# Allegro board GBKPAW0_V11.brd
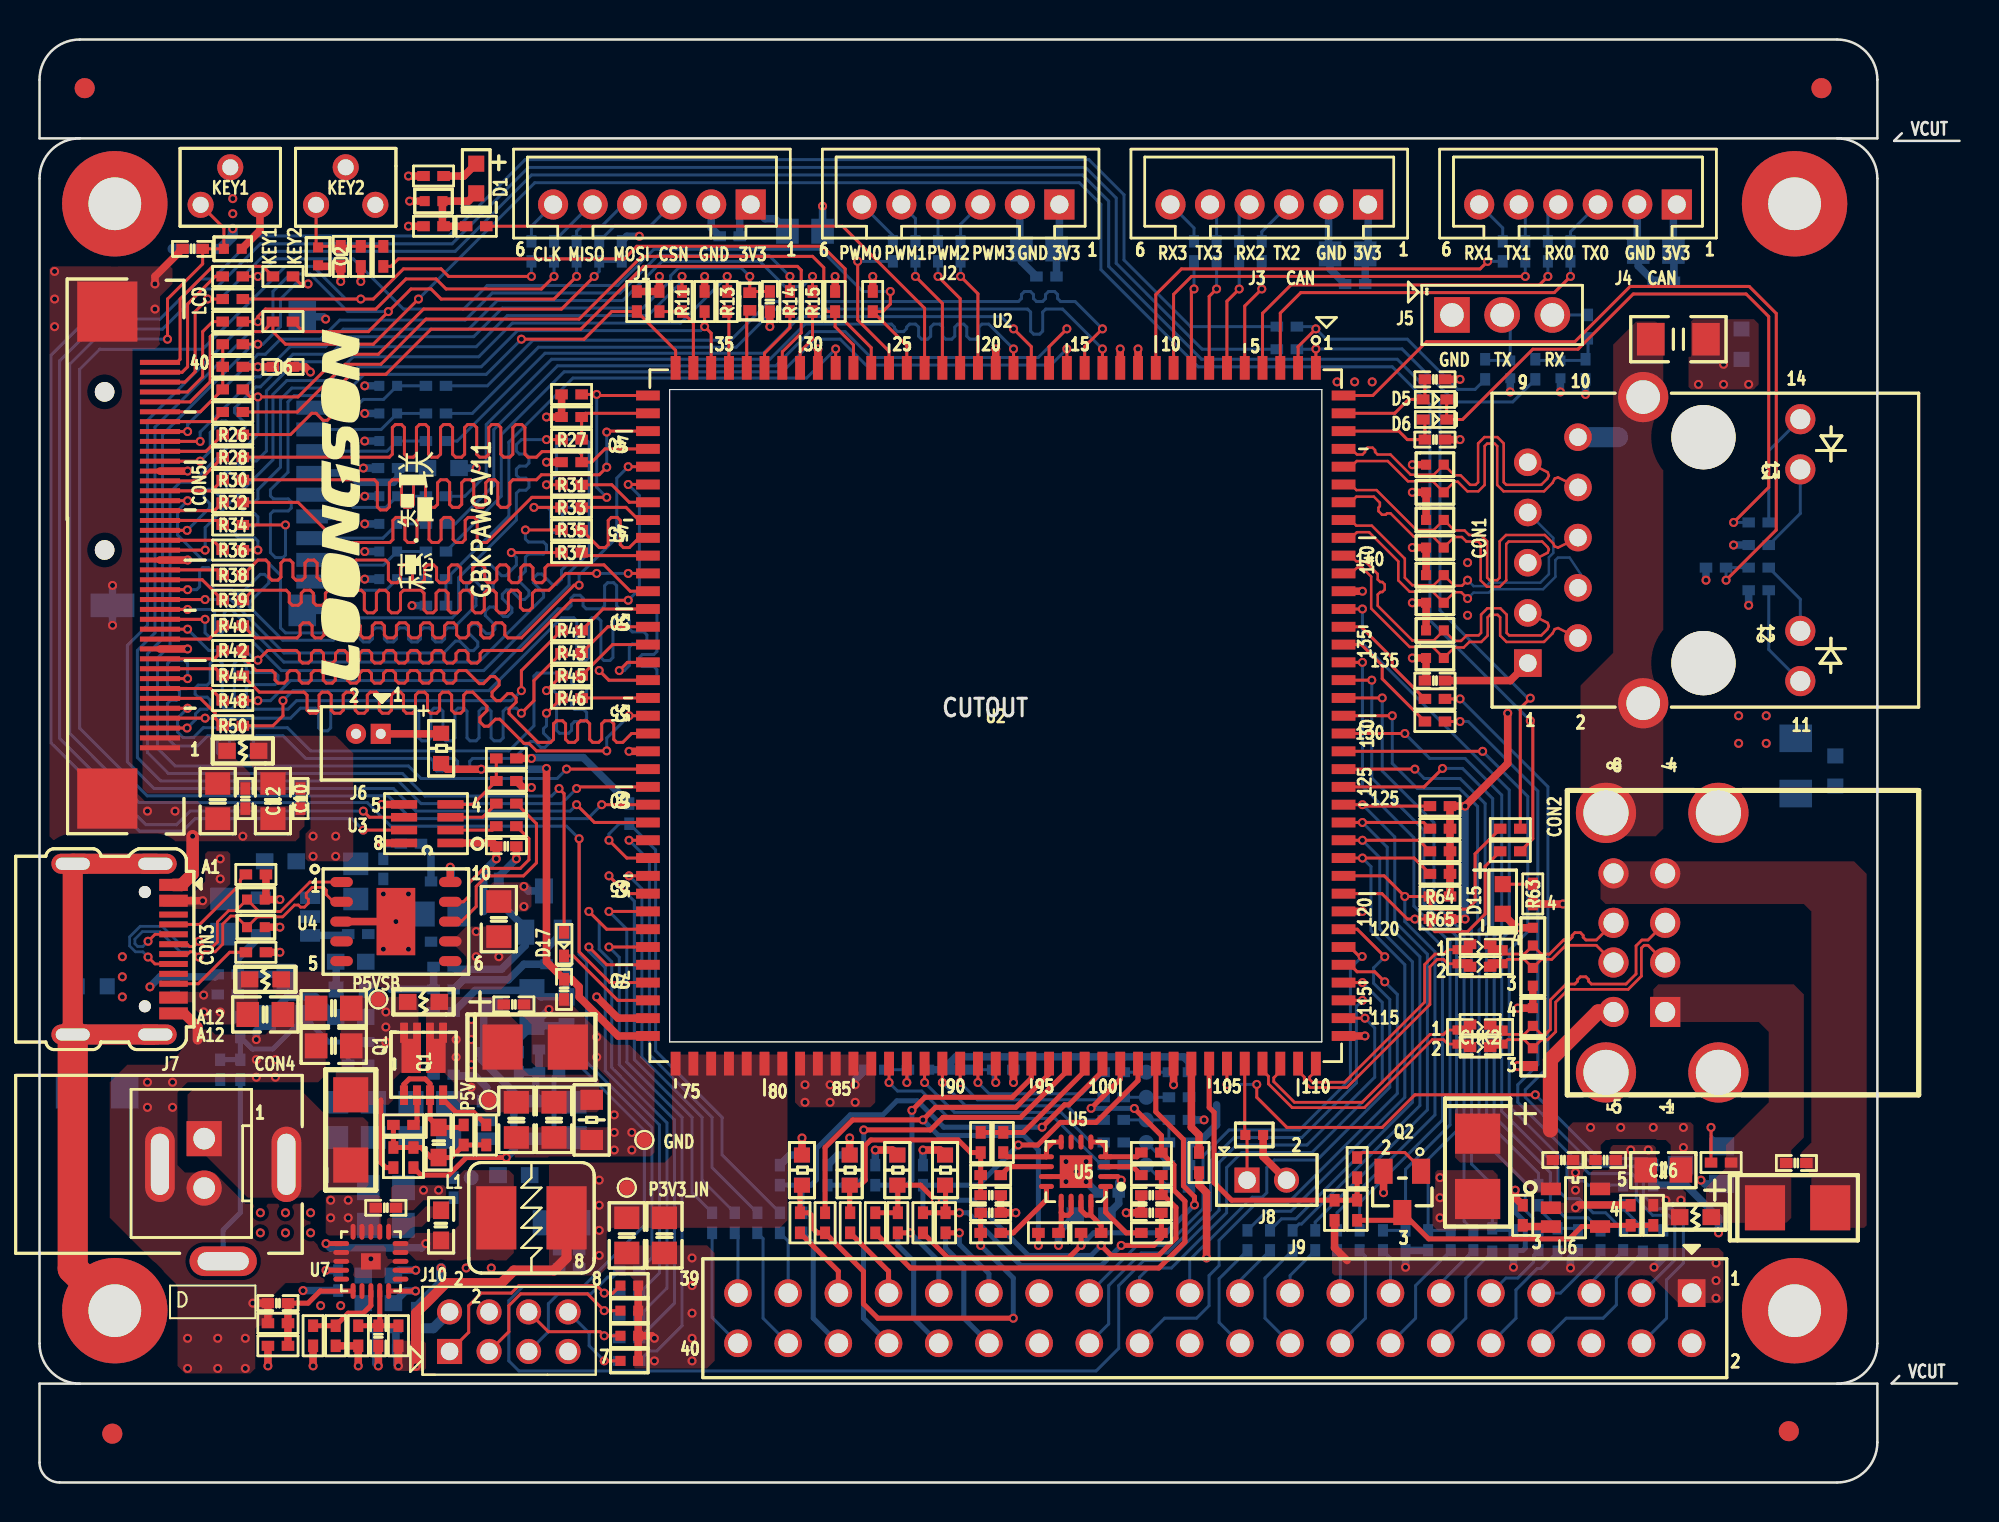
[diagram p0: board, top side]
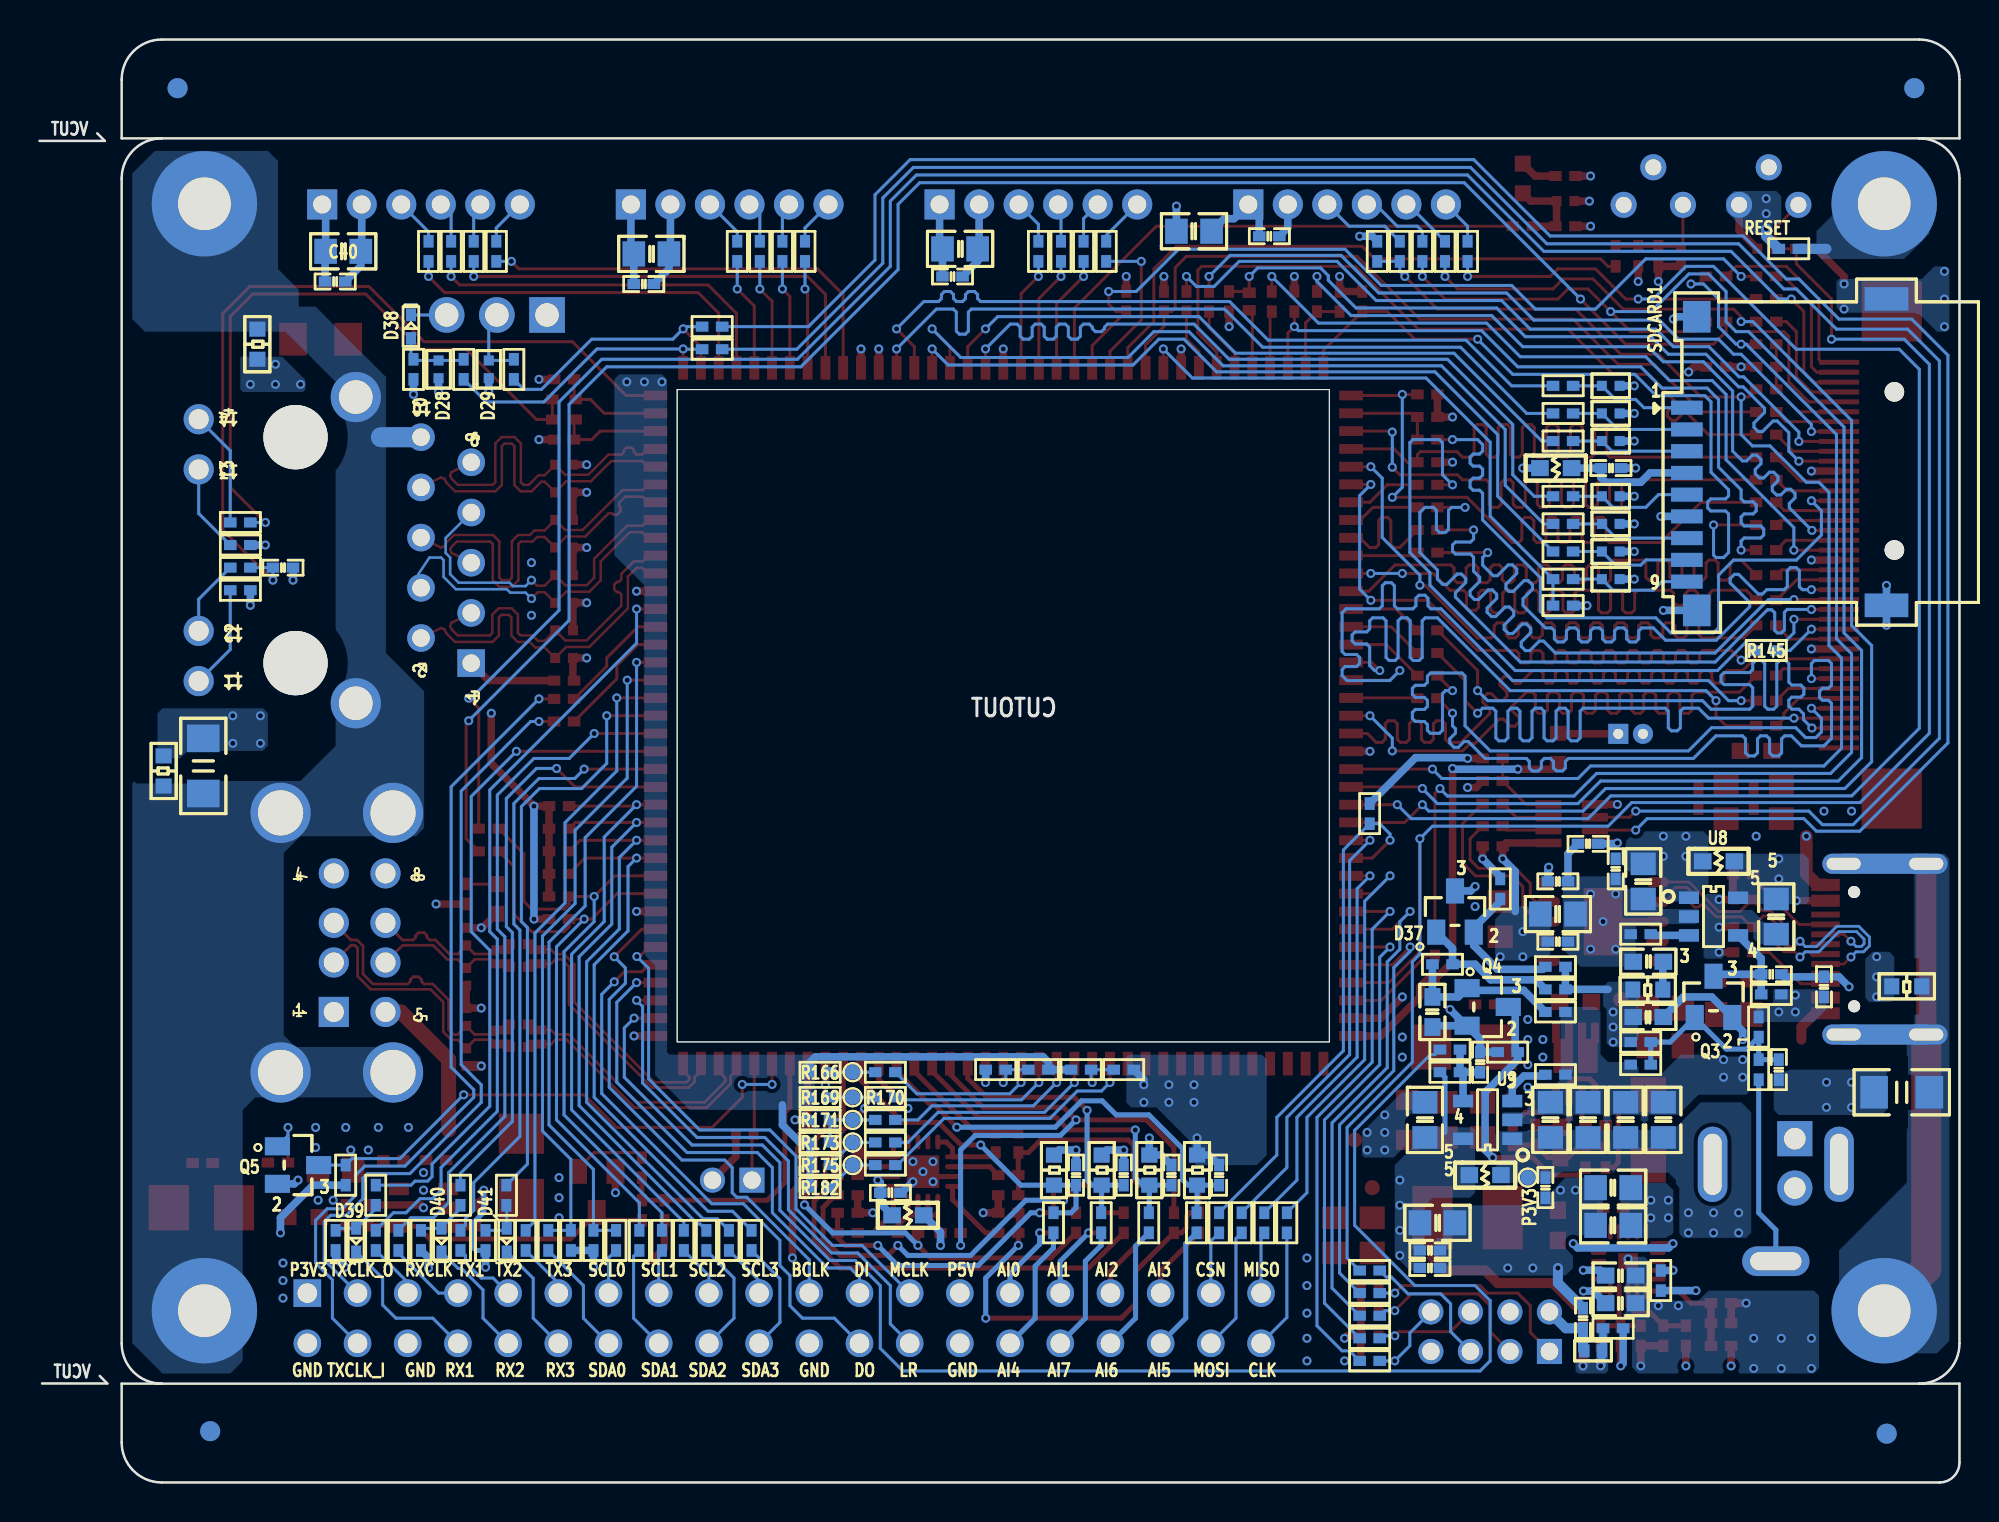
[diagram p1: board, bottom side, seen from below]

Outline 97.16 x 73 mm; copper layers: TOP, GND02, PWR03, BOTTOM. Coordinates in mm from the lower left corner of the outline.
Outline path: 2.03,68 0,68 0,70.97 arc(0.6,72.4) 2.03,73 90.97,73 arc(92.4,72.4) 93,70.97 93,68 90.97,68 ; 2.03,68 arc(0.6,67.4) 0,65.97 ; 2.03,68 arc(0.6,67.4) 0,65.97 ; 2.03,68 90.97,68 ; 2.03,68 90.97,68 ; 0,65.97 0,7.03 ; 0,65.97 0,7.03 ; 0,7.03 arc(0.6,5.6) 2.03,5 ; 0,7.03 arc(0.6,5.6) 2.03,5 ; 2.03,5 0,5 0,1.02 arc(0.3,0.3) 1.02,0 90.97,0 arc(92.4,0.6) 93,2.03 93,5 90.97,5 ; 2.03,5 90.97,5 ; 2.03,5 90.97,5 ; 90.97,68 arc(92.4,67.4) 93,65.97 ; 90.97,68 arc(92.4,67.4) 93,65.97 ; 90.97,5 arc(92.4,5.6) 93,7.03 ; 90.97,5 arc(92.4,5.6) 93,7.03 ; 93,65.97 93,7.03 ; 93,65.97 93,7.03 ; 94.11,5.39 93.73,5.01 97.03,5.01 ; 94.23,68.25 93.85,67.87 97.16,67.87 ; 31.89,55.29 31.89,22.29 64.89,22.29 64.89,55.29 31.89,55.29

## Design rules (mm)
net group CARD_DET: nets CARD_DET CPU_TIM1_CH1
net group CPU_JTAG_TCK: nets CPU_JTAG_TCK EJTAG_TCK
net group CPU_LCD_CLK: nets CPU_LCD_CLK LCD_CLK
net group CPU_LCD_DATA0: nets CPU_LCD_DATA0 LCD_B0
net group CPU_LCD_DATA1: nets CPU_LCD_DATA1 LCD_B1
net group CPU_LCD_DATA2: nets CPU_LCD_DATA2 LCD_B2
net group CPU_LCD_DATA3: nets CPU_LCD_DATA3 LCD_B3
net group CPU_LCD_DATA4: nets CPU_LCD_DATA4 LCD_B4
net group CPU_LCD_DATA5: nets CPU_LCD_DATA5 LCD_B5
net group CPU_LCD_DATA6: nets CPU_LCD_DATA6 LCD_B6
net group CPU_LCD_DATA7: nets CPU_LCD_DATA7 LCD_B7
net group CPU_LCD_DATA8: nets CPU_LCD_DATA8 LCD_G0
net group CPU_LCD_DATA9: nets CPU_LCD_DATA9 LCD_G1
net group CPU_LCD_DATA10: nets CPU_LCD_DATA10 LCD_G2
net group CPU_LCD_DATA11: nets CPU_LCD_DATA11 LCD_G3
net group CPU_LCD_DATA12: nets CPU_LCD_DATA12 LCD_G4
net group CPU_LCD_DATA13: nets CPU_LCD_DATA13 LCD_G5
net group CPU_LCD_DATA14: nets CPU_LCD_DATA14 LCD_G6
net group CPU_LCD_DATA15: nets CPU_LCD_DATA15 LCD_G7
net group CPU_LCD_DATA16: nets CPU_LCD_DATA16 LCD_R0
net group CPU_LCD_DATA17: nets CPU_LCD_DATA17 LCD_R1
net group CPU_LCD_DATA18: nets CPU_LCD_DATA18 LCD_R2
net group CPU_LCD_DATA19: nets CPU_LCD_DATA19 LCD_R3
net group CPU_LCD_DATA20: nets CPU_LCD_DATA20 LCD_R4
net group CPU_LCD_DATA21: nets CPU_LCD_DATA21 LCD_R5
net group CPU_LCD_DATA22: nets CPU_LCD_DATA22 LCD_R6
net group CPU_LCD_DATA23: nets CPU_LCD_DATA23 LCD_R7
net group CPU_LCD_EN: nets CPU_LCD_EN LCD_DE
net group CPU_LCD_HSYNC: nets CPU_LCD_HSYNC LCD_HSYNC
net group CPU_LCD_VSYNC: nets CPU_LCD_VSYNC LCD_VSYNC
net group CPU_SDIO1_CLK: nets CPU_SDIO1_CLK SDIO1_CLK
net group CPU_SDIO1_CMD: nets CPU_SDIO1_CMD SDIO1_CMD
net group CPU_SDIO1_DATA0: nets CPU_SDIO1_DATA0 SDIO1_DATA0
net group CPU_SDIO1_DATA1: nets CPU_SDIO1_DATA1 SDIO1_DATA1
net group CPU_SDIO1_DATA2: nets CPU_SDIO1_DATA2 SDIO1_DATA2
net group CPU_SDIO1_DATA3: nets CPU_SDIO1_DATA3 SDIO1_DATA3
net group CPU_USB0_DM: nets CPU_USB0_DM USB0_DM
net group CPU_USB0_DP: nets CPU_USB0_DP USB0_DP
net group CPU_USB1_DM: nets CPU_USB1_DM USB1_DM
net group CPU_USB1_DP: nets CPU_USB1_DP USB1_DP
net group EARTH: nets GND_EARTH_R N21978619
net group USB_D: nets USB_DN USB_DP
net group MDIO: nets P0_MDIO0+ P0_MDIO0- P0_MDIO2+ P0_MDIO2- P0_MDIO3+ P0_MDIO3-
nets with their own width: min track width 0.381; nets GND P3V3

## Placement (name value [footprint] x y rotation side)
C1  -  [C0402]  7.75 62.41 180 top
C2  -  [C0402]  15.24 62.03 270 top
C3  -  [C0402]  36.96 59.75 270 top
C4  -  [C1206]  82.93 57.84 180 top
C5  -  [C0402]  70.61 55.81 180 top
C6  -  [C0402]  12.32 56.44 0 top
C7  -  [C0402]  70.61 52.76 180 top
C8  -  [C0402]  70.61 40.57 180 top
C9  -  [C0402]  10.41 34.6 270 top
C10  -  [C0402]  13.21 34.6 270 top
C11  -  [C0805]  9.02 34.47 270 top
C12  -  [C0805]  11.81 34.47 270 top
C13  -  [C0402]  23.62 32.19 0 top
C14  -  [C0805]  23.24 28.5 270 top
C15  -  [C0402]  26.54 24.95 90 top
C16  -  [C0402]  24 24.19 0 top
C17  -  [C0805]  14.89 23.99 180 top
C18  -  [C0805]  11.43 23.68 180 top
C19  -  [C0805]  14.89 22.09 180 top
C20  -  [C0805]  24.13 18.34 270 top
C21  -  [C0805]  26.04 18.34 270 top
C22  -  [C0603]  20.19 17.2 90 top
C23  -  [C0402]  77.09 16.31 0 top
C24  -  [C0402]  79.25 16.31 180 top
C25  -  [C0402]  88.9 16.16 0 top
C26  -  [C0805]  82.17 15.8 0 top
C27  -  [C0402]  48.13 14.53 180 top
C28  -  [C0402]  56.26 14.53 0 top
C29  -  [C0402]  17.53 13.9 180 top
C30  -  [C0402]  48.13 13.64 180 top
C31  -  [C0402]  56.26 13.64 0 top
C32  -  [C0603]  20.32 13.01 270 top
C33  -  [C0805]  29.72 12.5 270 top
C34  -  [C0805]  31.62 12.5 270 top
C35  -  [C0402]  12.06 9.07 0 top
C36  -  [C0402]  17.14 7.42 270 top
C37  -  [C0805]  38.73 63.3 0 bottom
C38  -  [C0402]  34.92 63.05 180 bottom
C39  -  [C0805]  50.57 62.41 180 bottom
C40  -  [C0805]  81.79 62.29 180 bottom
C41  -  [C0805]  66.19 62.15 180 bottom
C42  -  [C0402]  50.95 61.01 180 bottom
C43  -  [C0402]  82.2 60.76 180 bottom
C44  -  [C0402]  66.58 60.63 180 bottom
C45  -  [C0402]  17.64 51.32 180 bottom
C46  -  [C0402]  84.84 46.28 0 bottom
C47  -  [C1206]  88.87 36.25 270 bottom
C48  -  [C0402]  18.8 32.31 0 bottom
C49  -  [C0402]  17.4 31.04 270 bottom
C50  -  [C0402]  20.32 30.41 180 bottom
C51  -  [C0805]  16 30.41 270 bottom
C52  -  [C0805]  20.32 28.76 0 bottom
C53  -  [C0805]  9.27 28.63 270 bottom
C54  -  [C0402]  20.32 27.36 180 bottom
C55  -  [C0603]  15.75 26.34 0 bottom
C56  -  [C0402]  9.52 25.71 180 bottom
C57  -  [C0402]  6.86 25.07 90 bottom
C58  -  [C0603]  26.67 23.8 270 bottom
C59  -  [C0603]  15.75 23.55 180 bottom
C60  -  [C0402]  24.26 21.26 270 bottom
C61  -  [C0402]  9.14 20.88 270 bottom
C62  -  [C1206]  2.92 19.74 180 bottom
C63  -  [C0805]  27.05 18.34 90 bottom
C64  -  [C0805]  20.7 18.34 90 bottom
C65  -  [C0805]  18.8 18.34 90 bottom
C66  -  [C0805]  16.89 18.34 90 bottom
C67  -  [C0805]  14.99 18.34 90 bottom
C68  -  [C0402]  44.7 15.55 270 bottom
C69  -  [C0402]  42.29 15.55 270 bottom
C70  -  [C0402]  39.88 15.55 270 bottom
C71  -  [C0402]  37.47 15.55 270 bottom
C72  -  [C0402]  20.95 14.91 270 bottom
C73  -  [C0805]  17.53 14.91 0 bottom
C74  -  [C0402]  54.1 14.66 0 bottom
C75  -  [C0805]  26.42 13.14 180 bottom
C76  -  [C0805]  17.53 13.01 0 bottom
C77  -  [C0402]  26.8 11.74 0 bottom
C78  -  [C0402]  26.8 10.85 0 bottom
C79  -  [C0603]  17.14 10.47 180 bottom
C80  -  [C0603]  17.14 9.07 180 bottom
C81  -  [C0402]  19.05 8.31 270 bottom
CHK1  -  [FB4-0805]  72.9 26.6 270 top
CHK2  -  [FB4-0805]  72.9 22.53 270 top
CON1  -  [RJ45-10-100-LED2-M]  75.31 41.45 270 top
CON2  -  [USB8-H-2X1_2]  82.26 23.8 90 top
CON3  TYPE_C_20  [TYPE_C_20_2]  2.73 26.98 270 top
CON4  -  [PWC3-250_2]  12.49 16.1 270 top
CON5  -  [FPC40-20]  6.1 46.92 270 top
D1  LED BLUE  [LEDS_19_21SYGC]  22.1 65.97 90 top
D2  -  [ESDPSA-0402]  19.94 64.83 0 top
D3  -  [ESDPSA-0402]  9.78 62.41 180 top
D4  -  [ESDPSA-0402]  14.1 62.03 90 top
D5  -  [DIODE_SOD923]  70.61 54.79 180 top
D6  -  [DIODE_SOD923]  70.61 53.78 180 top
D7  -  [ESDPSA-0402]  70.61 51.49 0 top
D8  -  [ESDPSA-0402]  70.61 50.09 0 top
D9  -  [ESDPSA-0402]  70.61 48.7 0 top
D10  -  [ESDPSA-0402]  70.61 47.3 0 top
D11  -  [ESDPSA-0402]  70.61 45.9 0 top
D12  -  [ESDPSA-0402]  70.61 44.51 0 top
D13  -  [ESDPSA-0402]  70.61 43.11 0 top
D14  -  [ESDPSA-0402]  70.61 41.71 0 top
D15  LED BLUE  [LEDS_19_21SYGC]  74.04 29.52 90 top
D16  -  [ESDPSA-0402]  10.95 29.49 0 top
D17  -  [DIODE_SOD923]  26.54 27.23 90 top
D18  -  [ESDPSA-0402]  10.95 28.09 0 top
D19  -  [ESDPSA-0402]  75.56 27.61 90 top
D20  -  [ESDPSA-0402]  75.56 25.58 270 top
D21  -  [ESDPSA-0402]  75.56 23.55 90 top
D22  -  [ESDPSA-0402]  75.56 21.52 270 top
D23  -  [ESDPSA-0402]  61.47 17.58 0 top
D24  -  [ESDPSA-0402]  29.84 9.96 180 top
D25  -  [ESDPSA-0402]  29.84 8.69 180 top
D26  -  [ESDPSA-0402]  29.84 7.42 180 top
D27  -  [ESDPSA-0402]  29.84 6.15 180 top
D28  -  [ESDPSA-0402]  76.96 56.32 90 bottom
D29  -  [ESDPSA-0402]  74.42 56.32 90 bottom
D30  -  [ESDPSA-0402]  17.65 55.48 0 bottom
D31  -  [ESDPSA-0402]  17.65 54.08 0 bottom
D32  -  [ESDPSA-0402]  17.65 52.69 0 bottom
D33  -  [ESDPSA-0402]  17.65 49.89 0 bottom
D34  -  [ESDPSA-0402]  17.65 48.5 0 bottom
D35  -  [ESDPSA-0402]  17.65 47.1 0 bottom
D36  -  [ESDPSA-0402]  17.65 45.7 0 bottom
D37  -  [SOT23-3]  25.53 28.88 180 bottom
D38  -  [DIODE_SOD923]  78.36 58.48 270 bottom
D39  -  [DIODE_SOD923]  81.13 12.26 90 bottom
D40  -  [DIODE_SOD923]  76.82 12.26 90 bottom
D41  -  [DIODE_SOD923]  73.51 12.26 90 bottom
EC1  -  [TC3528-21]  25.08 22.03 0 top
EC2  -  [TC3528-21]  72.77 15.99 270 top
EC3  -  [TC3528-21]  88.96 13.9 0 top
F1  -  [FUSE1206]  15.75 17.84 90 top
FB1  -  [FB0402]  35.94 59.75 90 top
FB2  -  [FB0603]  10.29 37.01 180 top
FB3  -  [FB0603]  11.43 25.46 180 top
FB4  -  [FB0603]  19.43 24.31 0 top
FB5  -  [FB0603]  83.8 13.42 0 top
FB6  -  [FB0603]  20.43 51.32 0 bottom
FB7  -  [FB0603]  12.19 31.42 0 bottom
FB8  -  [FB0603]  24 15.55 180 bottom
FB9  -  [FB0603]  53.21 13.52 0 bottom
FB129  -  [FB0402]  18.54 6.66 180 bottom
J1  B6B-PH-K(LF)(SN)  [BHEAD1X6_2MM_2]  30.99 64.66 180 top
J2  B6B-PH-K(LF)(SN)  [BHEAD1X6_2MM_2]  46.61 64.66 180 top
J3  B6B-PH-K(LF)(SN)  [BHEAD1X6_2MM_2]  62.23 64.66 180 top
J4  B6B-PH-K(LF)(SN)  [BHEAD1X6_2MM_2]  77.85 64.66 180 top
J5  12251103CNG0S115001  [HEAD3-100-N]  74.01 59.07 0 top
J6  A1251WV-2P  [BHEAD1X2_1]  16.64 37.39 180 top
J7  2_54_1X2PIN  [BHEAD1X2_2_54MM]  8.33 16.14 270 top
J8  -  [HEAD2-79]  62.1 15.3 0 top
J9  2_54_2X20PIN  [HEADER20X2-100]  59.47 8.31 180 top
J10  -  [HEAD4X2-79]  20.75 6.63 270 top
KEY1  -  [SW3_3050]  9.65 65.59 270 top
KEY2  -  [SW3_3050]  15.49 65.59 270 top
L1  -  [PL0504]  24.89 13.39 0 top
MH1  -  [HOLE_C210D105]  3.81 64.69 0 top
MH2  -  [HOLE_C210D105]  88.81 64.69 0 top
MH3  -  [HOLE_C210D105]  3.81 8.69 0 top
MH4  -  [HOLE_C210D105]  88.81 8.69 0 top
MK1  X_Mark Point  [ID-BOARD]  2.29 70.54 0 top
MK2  X_Mark Point  [ID-BOARD]  90.17 70.54 0 top
MK3  X_Mark Point  [ID-BOARD]  88.52 2.6 0 top
MK4  X_Mark Point  [ID-BOARD]  3.68 2.47 0 top
MK5  X_Mark Point  [ID-BOARD]  90.17 70.54 180 bottom
MK6  X_Mark Point  [ID-BOARD]  2.29 70.54 180 bottom
MK7  X_Mark Point  [ID-BOARD]  88.52 2.6 180 bottom
MK8  X_Mark Point  [ID-BOARD]  3.68 2.47 180 bottom
NOREF  -  []  70.85 62.96 90 top
NOREF#2  -  []  49.61 64.66 0 top
NOREF#3  -  []  40.31 63.56 90 top
NOREF#4  -  []  23.99 62.96 90 top
NOREF#5  -  []  55.93 67.06 90 top
NOREF#6  -  []  77.82 57.82 90 top
NOREF#7  -  []  69.95 57.56 0 top
NOREF#8  -  []  55.93 67.06 0 top
NOREF#9  -  []  69.95 60.57 0 top
NOREF#10  -  []  55.23 67.46 0 top
NOREF#11  -  []  23.99 62.96 90 top
NOREF#12  -  []  24.69 67.06 0 top
NOREF#13  -  []  69.95 57.56 90 top
NOREF#14  -  []  10.73 12.39 90 top
NOREF#15  -  []  8.33 14.89 90 top
NOREF#16  -  []  16.45 40.4 90 top
NOREF#17  -  []  39.61 62.96 0 top
NOREF#18  -  []  65.23 64.66 0 top
NOREF#19  -  []  55.23 62.96 90 top
NOREF#20  -  []  25.99 64.66 0 top
NOREF#21  -  []  71.55 67.06 90 top
NOREF#22  -  []  19.18 47.81 90 top
NOREF#23  -  []  24.69 63.56 90 top
NOREF#24  -  []  39.61 67.46 0 top
NOREF#25  -  []  40.31 67.06 90 top
NOREF#26  -  []  55.23 62.96 0 top
NOREF#27  -  []  71.55 67.06 0 top
NOREF#28  -  []  4.63 12.39 0 top
NOREF#29  -  []  71.47 59.07 90 top
NOREF#30  -  []  71.55 63.56 90 top
NOREF#31  -  []  39.61 62.96 90 top
NOREF#32  -  []  76.91 57.82 90 top
NOREF#33  -  []  23.99 67.46 0 top
NOREF#34  -  []  4.63 12.39 90 top
NOREF#35  -  []  40.31 67.06 0 top
NOREF#36  -  []  78.08 57.56 90 top
NOREF#37  -  []  23.99 62.96 0 top
NOREF#38  -  []  8.33 14.89 0 top
NOREF#39  -  []  24.69 67.06 90 top
NOREF#40  -  []  70.2 59.02 0 top
NOREF#41  -  []  72.85 64.66 0 top
NOREF#42  -  []  70.85 62.96 90 top
NOREF#43  -  []  76.55 59.07 0 top
NOREF#44  -  []  76.55 59.07 0 top
NOREF#45  -  []  55.93 63.56 90 top
NOREF#46  -  []  55.23 62.96 90 top
NOREF#47  -  []  0 7.03 0 top
NOREF#48  -  []  4.63 12.39 90 top
NOREF#49  -  []  71.47 59.07 0 top
NOREF#50  -  []  70.2 60.32 0 top
NOREF#51  -  []  39.61 62.96 90 top
NOREF#52  -  []  71.47 59.07 0 top
NOREF#53  -  []  70.85 62.96 0 top
NOREF#54  -  []  80.85 64.66 0 top
NOREF#55  -  []  8.33 17.39 0 top
NOREF#56  -  []  70.85 67.46 0 top
NOREF#57  -  []  76.55 59.07 90 top
NOREF#58  -  []  57.23 64.66 0 top
NOREF#59  -  []  41.61 64.66 0 top
NOREF#60  -  []  33.99 64.66 0 top
NOREF#61  -  []  90.97 5 90 top
Q1  -  [DFN6_3X3]  19.43 21.14 270 top
Q2  -  [SOT23-3]  68.96 14.7 180 top
Q3  -  [SOT23-3]  12.45 24.57 180 bottom
Q4  -  [SOT23-3]  23.88 24.06 270 bottom
Q5  -  [SOT23-3]  84.07 16.06 270 bottom
R1  -  [R0402]  19.94 66.1 0 top
R2  -  [R0402]  19.94 63.56 0 top
R3  -  [R0402]  22.1 63.56 0 top
R4  -  [R0402]  16.26 62.03 270 top
R5  -  [R0402]  17.4 62.03 270 top
R6  -  [R0402]  9.78 61.02 0 top
R7  -  [R0402]  12.32 61.02 180 top
R8  -  [R0402]  9.78 59.87 180 top
R9  -  [R0402]  30.23 59.75 90 top
R10  -  [R0402]  31.37 59.75 90 top
R11  -  [R0402]  32.51 59.75 90 top
R12  -  [R0402]  33.66 59.75 270 top
R13  -  [R0402]  34.8 59.75 90 top
R14  -  [R0402]  37.97 59.75 90 top
R15  -  [R0402]  39.12 59.75 90 top
R16  -  [R0402]  40.26 59.75 270 top
R17  -  [R0402]  42.16 59.75 270 top
R18  -  [R0402]  9.78 58.73 180 top
R19  -  [R0402]  12.32 58.73 180 top
R20  -  [R0402]  9.78 57.59 180 top
R21  -  [R0402]  9.78 56.44 0 top
R22  -  [R0402]  9.78 55.3 180 top
R23  -  [R0402]  26.92 55.05 0 top
R24  -  [R0402]  9.78 54.16 0 top
R25  -  [R0402]  26.92 53.9 0 top
R26  -  [R0402]  9.78 53.01 180 top
R27  -  [R0402]  26.92 52.76 180 top
R28  -  [R0402]  9.78 51.87 180 top
R29  -  [R0402]  26.92 51.62 0 top
R30  -  [R0402]  9.78 50.73 180 top
R31  -  [R0402]  26.92 50.47 180 top
R32  -  [R0402]  9.78 49.59 180 top
R33  -  [R0402]  26.92 49.33 180 top
R34  -  [R0402]  9.78 48.44 180 top
R35  -  [R0402]  26.92 48.19 180 top
R36  -  [R0402]  9.78 47.17 180 top
R37  -  [R0402]  26.92 47.05 180 top
R38  -  [R0402]  9.78 45.9 180 top
R39  -  [R0402]  9.78 44.63 180 top
R40  -  [R0402]  9.78 43.36 180 top
R41  -  [R0402]  26.92 43.11 180 top
R42  -  [R0402]  9.78 42.09 180 top
R43  -  [R0402]  26.92 41.97 180 top
R44  -  [R0402]  9.78 40.82 180 top
R45  -  [R0402]  26.92 40.82 180 top
R46  -  [R0402]  26.92 39.68 180 top
R47  -  [R0402]  70.61 39.64 180 top
R48  -  [R0402]  9.78 39.55 180 top
R49  -  [R0402]  70.61 38.5 180 top
R50  -  [R0402]  9.78 38.28 180 top
R51  -  [R0603]  20.32 37.14 270 top
R52  -  [R0402]  23.62 36.63 0 top
R53  -  [R0402]  23.62 35.49 180 top
R54  -  [R0402]  23.62 34.35 180 top
R55  -  [R0402]  70.87 34.22 180 top
R56  -  [R0402]  23.62 33.2 180 top
R57  -  [R0402]  70.87 33.08 180 top
R58  -  [R0402]  74.42 33.08 0 top
R59  -  [R0402]  70.87 31.93 180 top
R60  -  [R0402]  74.42 31.93 0 top
R61  -  [R0402]  70.87 30.79 180 top
R62  -  [R0402]  10.95 30.76 0 top
R63  -  [R0402]  75.56 29.77 90 top
R64  -  [R0402]  70.87 29.65 180 top
R65  -  [R0402]  70.87 28.5 180 top
R66  -  [R0402]  72.9 27.23 180 top
R67  -  [R0402]  10.95 26.82 0 top
R68  -  [R0402]  72.9 26.09 180 top
R69  -  [R0402]  72.9 23.17 180 top
R70  -  [R0402]  72.9 22.03 180 top
R71  -  [R0805]  27.94 18.34 90 top
R72  -  [R0402]  18.41 18.09 0 top
R73  -  [R0402]  21.46 17.58 270 top
R74  -  [R0402]  22.61 17.58 90 top
R75  -  [R0402]  47.62 17.2 90 top
R76  -  [R0402]  48.77 17.2 270 top
R77  -  [R0402]  56.26 16.69 180 top
R78  -  [R0402]  17.91 16.44 270 top
R79  -  [R0402]  18.92 16.44 90 top
R80  -  [R0402]  58.67 16.18 90 top
R81  -  [R0402]  85.09 16.18 180 top
R82  -  [R0402]  66.67 15.93 90 top
R83  -  [R0603]  38.58 15.8 270 top
R84  -  [R0603]  41 15.8 270 top
R85  -  [R0603]  43.41 15.8 270 top
R86  -  [R0603]  45.82 15.8 270 top
R87  -  [R0402]  48.13 15.55 0 top
R88  -  [R0402]  56.26 15.55 180 top
R89  -  [R0402]  65.53 13.77 270 top
R90  -  [R0402]  66.67 13.77 270 top
R91  -  [R0402]  75.06 13.52 90 top
R92  -  [R0402]  80.52 13.52 270 top
R93  -  [R0402]  81.66 13.52 270 top
R94  -  [R0402]  38.48 13.14 270 top
R95  -  [R0402]  39.75 13.14 90 top
R96  -  [R0402]  41.02 13.14 270 top
R97  -  [R0402]  42.29 13.14 270 top
R98  -  [R0402]  43.43 13.14 270 top
R99  -  [R0402]  44.7 13.14 270 top
R100  -  [R0402]  45.85 13.14 270 top
R101  -  [R0402]  48.13 12.63 0 top
R102  -  [R0402]  51.05 12.63 0 top
R103  -  [R0402]  53.21 12.63 0 top
R104  -  [R0402]  56.26 12.63 180 top
R105  -  [R0402]  12.06 8.06 180 top
R106  -  [R0402]  13.84 7.42 270 top
R107  -  [R0402]  14.99 7.42 270 top
R108  -  [R0402]  16.13 7.42 270 top
R109  -  [R0402]  18.16 7.42 270 top
R110  -  [R0402]  12.06 6.91 180 top
R111  -  [R0402]  8.64 62.41 180 bottom
R112  -  [R0402]  77.47 62.29 270 bottom
R113  -  [R0402]  76.33 62.29 270 bottom
R114  -  [R0402]  75.18 62.29 270 bottom
R115  -  [R0402]  74.04 62.29 270 bottom
R116  -  [R0402]  61.85 62.29 270 bottom
R117  -  [R0402]  60.71 62.29 270 bottom
R118  -  [R0402]  59.56 62.29 270 bottom
R119  -  [R0402]  58.42 62.29 270 bottom
R120  -  [R0402]  43.18 62.29 270 bottom
R121  -  [R0402]  44.32 62.29 270 bottom
R122  -  [R0402]  45.47 62.29 270 bottom
R123  -  [R0402]  46.61 62.29 270 bottom
R124  -  [R0402]  28.32 62.29 270 bottom
R125  -  [R0402]  27.18 62.29 270 bottom
R126  -  [R0402]  26.04 62.29 270 bottom
R127  -  [R0402]  24.89 62.29 270 bottom
R128  -  [R0402]  63.12 58.48 0 bottom
R129  -  [R0603]  86.13 57.59 270 bottom
R130  -  [R0402]  63.12 57.33 0 bottom
R131  -  [R0402]  75.69 56.32 270 bottom
R132  -  [R0402]  73.15 56.32 270 bottom
R133  -  [R0402]  20.06 55.48 180 bottom
R134  -  [R0402]  20.06 54.08 180 bottom
R135  -  [R0402]  20.06 52.69 180 bottom
R136  -  [R0402]  20.06 49.89 180 bottom
R137  -  [R0402]  86.99 48.57 180 bottom
R138  -  [R0402]  20.06 48.5 180 bottom
R139  -  [R0402]  86.99 47.43 180 bottom
R140  -  [R0402]  20.06 47.1 180 bottom
R141  -  [R0402]  86.99 46.28 180 bottom
R142  -  [R0402]  20.06 45.7 180 bottom
R143  -  [R0402]  86.99 45.14 180 bottom
R144  -  [R0402]  20.06 44.36 180 bottom
R145  -  [R0402]  9.78 42.09 180 bottom
R146  -  [R0603]  90.87 36 90 bottom
R147  -  [R0402]  23.24 30.03 270 bottom
R148  -  [R0402]  16.13 27.74 180 bottom
R149  -  [R0402]  20.45 26.09 0 bottom
R150  -  [R0603]  2.67 25.1 0 bottom
R151  -  [R0402]  20.45 24.95 180 bottom
R152  -  [R0603]  15.77 24.93 0 bottom
R153  -  [R0402]  9.52 24.69 180 bottom
R154  -  [R0402]  20.45 23.8 180 bottom
R155  -  [R0402]  10.16 23.04 90 bottom
R156  -  [R0402]  16.13 22.28 0 bottom
R157  -  [R0402]  25.78 21.9 180 bottom
R158  -  [R0402]  22.86 21.77 180 bottom
R159  -  [R0402]  16.13 21.14 180 bottom
R160  -  [R0402]  48.77 20.88 0 bottom
R161  -  [R0402]  46.61 20.88 180 bottom
R162  -  [R0402]  44.45 20.88 0 bottom
R163  -  [R0402]  42.29 20.88 180 bottom
R164  -  [R0402]  20.45 20.63 0 bottom
R165  -  [R0402]  10.16 20.88 90 bottom
R166  -  [R0402]  57.66 20.76 180 bottom
R167  -  [R0402]  54.36 20.76 0 bottom
R168  -  [R0402]  25.78 20.76 0 bottom
R169  -  [R0402]  57.66 19.49 180 bottom
R170  -  [R0402]  54.36 19.49 0 bottom
R171  -  [R0402]  57.66 18.34 180 bottom
R172  -  [R0402]  54.36 18.34 0 bottom
R173  -  [R0402]  57.66 17.2 180 bottom
R174  -  [R0402]  54.36 17.2 180 bottom
R175  -  [R0402]  57.66 16.06 180 bottom
R176  -  [R0402]  54.36 16.06 0 bottom
R177  -  [R0603]  45.82 15.8 270 bottom
R178  -  [R0603]  43.41 15.8 270 bottom
R179  -  [R0603]  41 15.8 270 bottom
R180  -  [R0603]  38.58 15.8 270 bottom
R181  -  [R0402]  81.66 15.55 270 bottom
R182  -  [R0402]  57.66 14.91 180 bottom
R183  -  [R0402]  45.85 13.14 270 bottom
R184  -  [R0402]  43.43 13.14 270 bottom
R185  -  [R0402]  41.02 13.14 270 bottom
R186  -  [R0402]  38.61 13.14 270 bottom
R187  -  [R0402]  37.47 13.14 90 bottom
R188  -  [R0402]  36.32 13.14 90 bottom
R189  -  [R0402]  35.18 13.14 90 bottom
R190  -  [R0402]  34.04 13.14 90 bottom
R191  -  [R0402]  82.17 12.25 90 bottom
R192  -  [R0402]  80.14 14.53 90 bottom
R193  -  [R0402]  80.14 12.25 90 bottom
R194  -  [R0402]  78.99 12.25 90 bottom
R195  -  [R0402]  77.85 12.25 90 bottom
R196  -  [R0402]  75.86 14.53 90 bottom
R197  -  [R0402]  75.86 12.25 90 bottom
R198  -  [R0402]  74.59 12.25 90 bottom
R199  -  [R0402]  73.53 14.53 90 bottom
R200  -  [R0402]  72.55 12.25 90 bottom
R201  -  [R0402]  71.41 12.25 90 bottom
R202  -  [R0402]  70.27 12.25 90 bottom
R203  -  [R0402]  69.13 12.25 90 bottom
R204  -  [R0402]  67.98 12.25 90 bottom
R205  -  [R0402]  66.8 12.25 90 bottom
R206  -  [R0402]  65.66 12.25 90 bottom
R207  -  [R0402]  64.55 12.25 90 bottom
R208  -  [R0402]  63.41 12.25 90 bottom
R209  -  [R0402]  62.27 12.25 90 bottom
R210  -  [R0402]  61.12 12.25 90 bottom
R211  -  [R0402]  29.84 10.72 180 bottom
R212  -  [R0402]  15.11 10.22 270 bottom
R213  -  [R0402]  29.84 9.58 180 bottom
R214  -  [R0402]  29.84 8.44 180 bottom
R215  -  [R0402]  29.84 7.29 0 bottom
R216  -  [R0402]  17.53 7.8 0 bottom
R217  -  [R0402]  29.84 6.15 0 bottom
R218  -  [R0402]  78.23 56.32 90 bottom
R219  -  [R0402]  29.84 33.84 270 bottom
R220  -  [R0402]  29.46 62.29 270 bottom
R221  -  [R0402]  26.16 26.22 0 bottom
SDCARD1  TF-115-BCP9  [SDCARD8_3]  6.54 52.13 90 bottom
TP1  -  [TP-SMD]  17.14 24.44 180 top
TP2  -  [TP-SMD]  22.73 19.36 180 top
TP3  -  [TP-SMD]  30.61 17.33 0 top
TP4  -  [TP-SMD]  29.72 14.91 270 top
TP5  -  [TP-SMD]  56.01 20.76 90 bottom
TP6  -  [TP-SMD]  56.01 19.49 90 bottom
TP7  -  [TP-SMD]  56.01 18.34 90 bottom
TP8  -  [TP-SMD]  56.01 17.2 270 bottom
TP9  -  [TP-SMD]  56.01 16.06 270 bottom
TP10  -  [TP-SMD]  21.84 15.42 90 bottom
U2  -  [LS2K0300_STAMP]  48.39 38.79 270 top
U3  -  [SOT23-8]  19.62 33.33 180 top
U4  CH340K  [ESSOP10_SMD77X124]  18.03 28.38 270 top
U5  -  [QFN16-050-3X3]  52.45 15.73 180 top
U6  -  [SOT23-5]  77.72 13.9 270 top
U7  -  [QFN3X3_20]  16.77 11.19 270 top
U8  -  [SOT23-5]  12.45 28.63 270 bottom
U9  -  [SOT23-5]  23.88 18.34 90 bottom

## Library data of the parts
C1 C3 C4 C8 C9 C11-C45 C47-C81 = C
C2 C6 C10 = C: signal model: C_C0402_0.1UF_16V_0.1UF_16V
C5 C7 C46 = C: signal model: C_C0402_100PF50V_100PF_50V
CHK1 = CHOCK: signal model: CHOCK_FB4-0805_90@100MHZ_300MA
CHK2 = CHOCK: signal model: CHOCK_FB4-0805_90@100MHZ_300MA_90@100MHZ_300mA
CON1 = J0191113011HR1
CON2 = J02UB1112C2FC1
CON3 = TYPE_C_0: Tolerance: TOL
CON4 = J03DC6D0011EC1
CON5 = J1812400511HI1_0
D1 D15 = LED_0: Tolerance: TOL
D2-D4 D16 D18-D29 = ESD DIODE_0
D5 D6 D17 D38-D41 = DIODE SCHOTTKY_AC
D7-D14 D30-D36 = ESD DIODE_0: signal model: ESD_DIODE_0_ESDPSA-0402_KESD531
D37 = TL431_0
EC1-EC3 = CT
F1 = 0451005
FB1 = BEAD: signal model: BEAD_FB0402_600@100MHZ_0.3A
FB2-FB9 FB129 = BEAD
J1-J4 = 2_00_1X6PIN
J5 = 2_54_1X3PIN
J6 = 1_25_1x2pin: Tolerance: TOL
J7 = 1_25_1x2pin
J8 = 2_00_0
J9 = 2_54_2X20PIN: Tolerance: TOL
J10 = 2_00_2
KEY1 KEY2 = K2-1109DE
L1 = INDUCTOR
MH1-MH4 = HOLE_3
MK1-MK8 = MARK: User Part Number: HAMP; Tolerance: #TOL
Q1 = SI7232DN-T1-GE3
Q2 Q5 = L2N7002LT1G
Q3 Q4 = 2N7002LT1G
R1-R7 R9 R10 R12 R16-R18 R21 R23-R25 R29 R47 R49 R51-R57 R59 R61-R63 R67 R71-R132 R137 R139 R141 R143 R144 R146-R165 R167 R168 R171 R172 R174 R176-R181 R183-R221 = R
R8 R19 R20 R22 R58 R60 = R: signal model: R_R0402_22R1%0402_R11-0220T12-W_22R1%0402
R11 R13-R15 R26-R28 R30-R46 R48 R50 R145 = R: signal model: R_R0402_0R_5%_0R_5%
R64 R65 R166 R169 R173 R175 R182 = R: signal model: R_R0402_4.7K_5%_4.7K_5%
R66 R68-R70 = R: signal model: R_R0402_0R_5%
R133-R136 R138 R142 = R: signal model: R_R0402_22R_5%
R140 R170 = R: signal model: R_R0402_33R_5%_33R_5%
SDCARD1 = SDC_8P-3_60: Tolerance: TOL
TP1-TP10 = SD_TSTR
U2 = LS2K0300_STAMP
U3 = SGM4553
U4 = CH340E_0: Tolerance: TOL
U5 = RS6334
U6 = SGM2588
U7 = JW5079A
U8 U9 = SY6280

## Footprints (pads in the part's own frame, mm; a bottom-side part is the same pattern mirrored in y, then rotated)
BHEAD1X2_1
  rect 1.016x1.016 hole 0.508: 1(-0.625,-0.48)
  round 1.016 hole 0.508: 2(0.625,-0.48)
BHEAD1X2_2_54MM
  rect 1.778x1.778 hole 1.092: 1(-1.25,0)
  round 1.778 hole 1.092: 2(1.25,0)
BHEAD1X6_2MM_2
  rect 1.524x1.524 hole 0.914: 1(-5,0)
  round 1.524 hole 0.914: 2(-3,0) 3(-1,0) 4(1,0) 5(3,0) 6(5,0)
C0402
  rect 0.635x0.508 smd: 1(-0.508,0) 2(0.508,0)
C0603
  rect 0.889x0.813 smd: 1(-0.762,0) 2(0.762,0)
C0805
  rect 1.143x1.27 smd: 1(-0.889,0) 2(0.889,0)
C1206
  rect 1.397x1.651 smd: 1(-1.397,0) 2(1.397,0)
DFN6_3X3
  rect 0.991x0.406 smd: 1(1.546,-0.99) 2(1.546,-0.33) 3(1.546,0.331) 4(1.546,0.991)
  custom 0.265x0.265 smd: 5(-0.855,0.658) 8(-0.855,-0.657)
DIODE_SOD923
  rect 0.635x0.508 smd: A(0.593,0) C(-0.593,0)
ESDPSA-0402
  rect 0.508x0.508 smd: 1(-0.45,0) 2(0.45,0)
ESSOP10_SMD77X124
  oval 0.508x1.143 smd: 1(-2,-2.75) 2(-1,-2.75) 3(0,-2.75) 4(1,-2.75) 5(2,-2.75) 6(2,2.75) 7(1,2.75) 8(0,2.75) 9(-1,2.75) 10(-2,2.75)
  rect 3.404x1.956 smd: 11(0,0)
FB4-0805
  rect 0.457x1.016 smd: 1(-0.356,-0.889) 2(0.356,-0.889) 3(0.356,0.889) 4(-0.356,0.889)
FB0402
  rect 0.533x0.66 smd: 1(-0.446,0) 2(0.446,0)
FB0603
  rect 0.889x0.813 smd: 1(-0.8,0) 2(0.8,0)
FPC40-20
  rect 0.254x2.032 smd: 1(9.75,0) 2(9.25,0) 3(8.75,0) 4(8.25,0) 5(7.75,0) 6(7.25,0) 7(6.75,0) 8(6.25,0) 9(5.75,0) 10(5.25,0) 11(4.75,0) 12(4.25,0) 13(3.75,0) 14(3.25,0) 15(2.75,0) 16(2.25,0) 17(1.75,0) 18(1.25,0) 19(0.75,0) 20(0.25,0) 21(-0.25,0) 22(-0.75,0) 23(-1.25,0) 24(-1.75,0) 25(-2.25,0) 26(-2.75,0) 27(-3.25,0) 28(-3.75,0) 29(-4.25,0) 30(-4.75,0) 31(-5.25,0) 32(-5.75,0) 33(-6.25,0) 34(-6.75,0) 35(-7.25,0) 36(-7.75,0) 37(-8.25,0) 38(-8.75,0) 39(-9.25,0) 40(-9.75,0)
  rect 3.048x3.048 smd: 41(-12.319,-2.667) 42(12.319,-2.667)
FUSE1206
  rect 1.778x1.778 smd: 1(-1.778,0) 2(1.778,0)
HEAD2-79
  rect 1.27x1.27 hole 0.889: 1(-1,0)
  round 1.27 hole 0.889: 2(1,0)
HEAD3-100-N
  rect 1.803x1.803 hole 1.194: 1(-2.54,0)
  round 1.803 hole 1.194: 2(0,0) 3(2.54,0)
HEAD4X2-79
  rect 1.27x1.27 hole 0.889: 1(0,0)
  round 1.27 hole 0.889: 2(-2,0) 3(0,2) 4(-2,2) 5(0,4) 6(-2,4) 7(0,6) 8(-2,6)
HEADER20X2-100
  rect 1.397x1.397 hole 0.991: 1(-24.13,-1.27)
  round 1.397 hole 0.991: 2(-24.13,1.27) 3(-21.59,-1.27) 4(-21.59,1.27) 5(-19.05,-1.27) 6(-19.05,1.27) 7(-16.51,-1.27) 8(-16.51,1.27) 9(-13.97,-1.27) 10(-13.97,1.27) 11(-11.43,-1.27) 12(-11.43,1.27) 13(-8.89,-1.27) 14(-8.89,1.27) 15(-6.35,-1.27) 16(-6.35,1.27) 17(-3.81,-1.27) 18(-3.81,1.27) 19(-1.27,-1.27) 20(-1.27,1.27) 21(1.27,-1.27) 22(1.27,1.27) 23(3.81,-1.27) 24(3.81,1.27) 25(6.35,-1.27) 26(6.35,1.27) 27(8.89,-1.27) 28(8.89,1.27) 29(11.43,-1.27) 30(11.43,1.27) 31(13.97,-1.27) 32(13.97,1.27) 33(16.51,-1.27) 34(16.51,1.27) 35(19.05,-1.27) 36(19.05,1.27) 37(21.59,-1.27) 38(21.59,1.27) 39(24.13,-1.27) 40(24.13,1.27)
HOLE_C210D105
  round 5.334 hole 2.667: 1(0,0)
ID-BOARD
  round 1.016 smd: 1(0,0)
LEDS_19_21SYGC
  rect 0.813x0.813 smd: A(0.75,0) C(-0.75,0)
LS2K0300_STAMP
  rect 1.2x0.5 smd: 1(-17.601,16.2) 2(-17.601,15.3) 3(-17.601,14.4) 4(-17.601,13.5) 5(-17.601,12.6) 6(-17.601,11.7) 7(-17.601,10.8) 8(-17.601,9.9) 9(-17.601,9) 10(-17.601,8.1) 11(-17.601,7.2) 12(-17.601,6.3) 13(-17.601,5.4) 14(-17.601,4.5) 15(-17.601,3.6) 16(-17.601,2.7) 17(-17.601,1.8) 18(-17.601,0.9) 19(-17.601,0) 20(-17.601,-0.9) 21(-17.601,-1.8) 22(-17.601,-2.7) 23(-17.601,-3.6) 24(-17.601,-4.5) 25(-17.601,-5.4) 26(-17.601,-6.3) 27(-17.601,-7.2) 28(-17.601,-8.1) 29(-17.601,-9) 30(-17.601,-9.9) 31(-17.601,-10.8) 32(-17.601,-11.7) 33(-17.601,-12.6) 34(-17.601,-13.5) 35(-17.601,-14.4) 36(-17.601,-15.3) 37(-17.601,-16.2) 75(17.601,-16.2) 76(17.601,-15.3) 77(17.601,-14.4) 78(17.601,-13.5) 79(17.601,-12.6) 80(17.601,-11.7) 81(17.601,-10.8) 82(17.601,-9.9) 83(17.601,-9) 84(17.601,-8.1) 85(17.601,-7.2) 86(17.601,-6.3) 87(17.601,-5.4) 88(17.601,-4.5) 89(17.601,-3.6) 90(17.601,-2.7) 91(17.601,-1.8) 92(17.601,-0.9) 93(17.601,0) 94(17.601,0.9) 95(17.601,1.8) 96(17.601,2.7) 97(17.601,3.6) 98(17.601,4.5) 99(17.601,5.4) 100(17.601,6.3) 101(17.601,7.2) 102(17.601,8.1) 103(17.601,9) 104(17.601,9.9) 105(17.601,10.8) 106(17.601,11.7) 107(17.601,12.6) 108(17.601,13.5) 109(17.601,14.4) 110(17.601,15.3) 111(17.601,16.2)
  rect 0.5x1.2 smd: 38(-16.2,-17.601) 39(-15.3,-17.601) 40(-14.4,-17.601) 41(-13.5,-17.601) 42(-12.6,-17.601) 43(-11.7,-17.601) 44(-10.8,-17.601) 45(-9.9,-17.601) 46(-9,-17.601) 47(-8.1,-17.601) 48(-7.2,-17.601) 49(-6.3,-17.601) 50(-5.4,-17.601) 51(-4.5,-17.601) 52(-3.6,-17.601) 53(-2.7,-17.601) 54(-1.8,-17.601) 55(-0.9,-17.601) 56(0,-17.601) 57(0.9,-17.601) 58(1.8,-17.601) 59(2.7,-17.601) 60(3.6,-17.601) 61(4.5,-17.601) 62(5.4,-17.601) 63(6.3,-17.601) 64(7.2,-17.601) 65(8.1,-17.601) 66(9,-17.601) 67(9.9,-17.601) 68(10.8,-17.601) 69(11.7,-17.601) 70(12.6,-17.601) 71(13.5,-17.601) 72(14.4,-17.601) 73(15.3,-17.601) 74(16.2,-17.601) 112(16.2,17.601) 113(15.3,17.601) 114(14.4,17.601) 115(13.5,17.601) 116(12.6,17.601) 117(11.7,17.601) 118(10.8,17.601) 119(9.9,17.601) 120(9,17.601) 121(8.1,17.601) 122(7.2,17.601) 123(6.3,17.601) 124(5.4,17.601) 125(4.5,17.601) 126(3.6,17.601) 127(2.7,17.601) 128(1.8,17.601) 129(0.9,17.601) 130(0,17.601) 131(-0.9,17.601) 132(-1.8,17.601) 133(-2.7,17.601) 134(-3.6,17.601) 135(-4.5,17.601) 136(-5.4,17.601) 137(-6.3,17.601) 138(-7.2,17.601) 139(-8.1,17.601) 140(-9,17.601) 141(-9.9,17.601) 142(-10.8,17.601) 143(-11.7,17.601) 144(-12.6,17.601) 145(-13.5,17.601) 146(-14.4,17.601) 147(-15.3,17.601) 148(-16.2,17.601)
PL0504
  rect 2.032x3.2 smd: 1(-1.778,0) 2(1.778,0)
PWC3-250_2
  oval 3.81x1.499 hole 3.099x0.914: 1(0,0) 2(0,-6.4)
  oval 1.499x3.404 hole 0.914x2.591: 3(4.902,-3.2)
QFN3X3_20
  oval 0.8x0.25 smd: 1(-1.5,0.9) 2(-1.5,0.45) 3(-1.5,0) 4(-1.5,-0.45) 5(-1.5,-0.9) 11(1.5,-0.9) 12(1.5,-0.45) 13(1.5,0) 14(1.5,0.45) 15(1.5,0.9)
  oval 0.25x0.8 smd: 6(-0.9,-1.5) 7(-0.45,-1.5) 8(0,-1.5) 9(0.45,-1.5) 10(0.9,-1.5) 16(0.9,1.5) 17(0.45,1.5) 18(0,1.5) 19(-0.45,1.5) 20(-0.9,1.5)
  rect 0.83x1 smd: 21(0,0)
QFN16-050-3X3
  oval 0.762x0.254 smd: 1(-1.498,0.751) 2(-1.498,0.25) 3(-1.498,-0.25) 4(-1.498,-0.751) 9(1.498,-0.751) 10(1.498,-0.25) 11(1.498,0.25) 12(1.498,0.751)
  oval 0.254x0.762 smd: 5(-0.751,-1.498) 6(-0.25,-1.498) 7(0.25,-1.498) 8(0.751,-1.498) 13(0.751,1.498) 14(0.25,1.498) 15(-0.25,1.498) 16(-0.751,1.498)
  rect 1.651x1.651 smd: 17(0,0)
R0402
  rect 0.635x0.508 smd: 1(-0.508,0) 2(0.508,0)
R0603
  rect 0.762x0.813 smd: 1(-0.762,0) 2(0.762,0)
R0805
  rect 1.016x1.143 smd: 1(-1.016,0) 2(1.016,0)
RJ45-10-100-LED2-M
  round 3.251 hole 3.251 unplated: (-11.43,8.89) (0,8.89)
  rect 1.397x1.397 hole 0.889: 1(0,0)
  round 1.397 hole 0.889: 2(-1.27,2.54) 3(-2.54,0) 4(-3.81,2.54) 5(-5.08,0) 6(-6.35,2.54) 7(-7.62,0) 8(-8.89,2.54) 9(-10.16,0) 10(-11.43,2.54)
  round 1.524 hole 1.016: 11(0.91,13.79) 12(-1.63,13.79) 13(-9.8,13.79) 14(-12.34,13.79)
  round 2.54 hole 1.702: 15(-13.46,5.84) 16(2.03,5.84)
SDCARD8_3
  round 0.991 hole 0.991 unplated: (-4.95,-3.25) (3.05,-3.25)
  rect 0.711x1.6 smd: 1(2.25,7.25) 2(1.15,7.25) 3(0.05,7.25) 4(-1.05,7.25) 5(-2.15,7.25) 6(-3.25,7.25) 7(-4.35,7.25) 8(-5.45,7.25) 9(-6.55,7.25)
  rect 1.6x1.397 smd: 11(6.85,6.75) 12(-8.004,6.75)
  rect 1.194x2.21 smd: 13(7.75,-2.85) 14(-7.75,-2.85)
SOT23-3
  rect 0.914x1.27 smd: 1(-0.95,-1.043) 2(0.95,-1.043) 3(0,1.043)
SOT23-5
  rect 0.635x1.016 smd: 1(-0.953,-1.245) 2(0,-1.245) 3(0.953,-1.245) 4(0.953,1.245) 5(-0.953,1.245)
SOT23-8
  rect 1.321x0.432 smd: 1(-1.175,0.975) 2(-1.175,0.325) 3(-1.175,-0.325) 4(-1.175,-0.975) 5(1.175,-0.975) 6(1.175,-0.325) 7(1.175,0.325) 8(1.175,0.975)
SW3_3050
  round 1.321 hole 0.813: 1(0.95,1.5) 2(0.95,-1.5) 3(-0.95,0)
TC3528-21
  rect 2.032x2.286 smd: 1(-1.651,0) 2(1.651,0)
TP-SMD
  round 0.762 smd: 1(0,0)
TYPE_C_20_2
  round 0.61 hole 0.61 unplated: (-2.89,2.6) (2.89,2.6)
  rect 0.61x1.448 smd: A1(-3.25,4.05) A4(-2.45,4.05) A9(2.45,4.05) A12(3.25,4.05)
  rect 0.305x1.448 smd: A5(-1.25,4.05) A6(-0.25,4.05) A7(0.25,4.05) A8(1.25,4.05) B5(1.75,4.05) B6(0.75,4.05) B7(-0.75,4.05) B8(-1.75,4.05)
  oval 1.016x2.159 hole 0.61x1.727: S1(-4.32,3.13) S2(4.32,3.13) S3(-4.32,-1.05) S4(4.32,-1.05)
USB8-H-2X1_2
  rect 1.524x1.524 hole 1.016: 1(0,0)
  round 1.524 hole 1.016: 2(2.502,0) 3(4.508,0) 4(7.01,0) 5(0,2.616) 6(2.502,2.616) 7(4.508,2.616) 8(7.01,2.616)
  round 3.048 hole 2.286: 9(-3.061,2.997) 10(10.071,2.997) 11(-3.061,-2.692) 12(10.071,-2.692)

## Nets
GND: C1.2 C2.2 C3.2 C4.1 C5.1 C6.2 C7.1 C8.2 C9.2 C10.2 C11.2 C12.2 C13.2 C14.1 C15.1 C16.2 C17.2 C18.1 C19.2 C20.2 C21.2 C23.2 C24.2 C25.2 C26.2 C27.1 C28.1 C29.1 C30.1 C31.1 C33.2 C34.2 C35.1 C37.2 C38.2 C39.2 C40.2 C41.2 C42.2 C43.2 C44.2 C45.2 C46.1 C47.1 C48.2 C49.2 C50.2 C51.2 C52.1 C53.2 C54.2 C55.2 C56.2 C57.2 C58.2 C59.2 C60.1 C61.2 C62.1 C63.2 C64.2 C65.2 C66.2 C67.2 C68.1 C69.1 C70.1 C71.1 C72.2 C73.2 C74.1 C75.2 C76.2 C77.1 C78.1 C79.2 C80.2 C81.1 CON2.4(CON_PIN[14]) CON2.8(CON_PIN[18]) CON3.A1(GND1) CON3.A12(GND2) CON4.2(VDD) CON5.11 CON5.20 CON5.29 CON5.41 CON5.42 D2.1 D3.1 D4.1 D7.1 D8.1 D9.1 D10.1 D11.1 D12.1 D13.1 D14.1 D15.C(CATHODE) D16.2 D18.2 D19.2 D20.2 D21.2 D22.2 D23.2 D24.1 D25.1 D26.1 D27.1 D28.1 D29.1 D30.1 D31.1 D32.1 D33.1 D34.1 D35.1 D36.1 D37.3(ANODE) EC1.2 EC2.2 EC3.2 J1.2 J2.2 J3.2 J4.2 J5.1 J6.2 J7.2 J8.2 J9.2 J9.6 J9.22 J9.28 J10.7 KEY1.1 KEY2.1 Q2.2(SOURCE) Q3.2(SOURCE) Q4.2(SOURCE) Q5.2(SOURCE) R9.2 R10.2 R53.1 R62.2 R67.2 R71.1 R83.1 R84.1 R85.1 R86.1 R92.1 R105.2 R107.2 R108.2 R111.1 R129.2 R139.2 R146.2 R147.1 R148.1 R150.2 R154.2 R158.1 R159.1 R160.2 R163.2 R164.1 R171.1 R177.1 R178.1 R179.1 R180.1 SDCARD1.6(VSS) SDCARD1.11(GND#11) SDCARD1.12(GND#12) SDCARD1.13(GND#13) SDCARD1.14(GND#14) TP3.1 U2.11 U2.12 U2.19 U2.29 U2.58 U2.73 U2.82 U2.83 U2.84 U2.85 U2.86 U2.94 U2.103 U2.112 U2.119 U2.137 U3.5(GND) U4.3(GND) U4.11(E_GND) U5.11(V-) U5.17(GND) U6.2(GND) U7.7(GND1) U7.8(GND2) U7.18(GND3) U7.21(GND4) U8.2(GND) U9.2(GND)
GND_EARTH_L: C62.2 CON3.S1(SHIELD1) CON3.S2(SHIELD2) CON3.S3(SHIELD3) CON3.S4(SHIELD4) MH3.1 R150.1
GND_EARTH_R: C4.2 C47.2 CON1.10 CON1.15 CON1.16 CON2.9(SH1) CON2.10(SH2) CON2.11(SH3) CON2.12(SH4) MH2.1 MH4.1 R129.1 R146.1
P3V3: C6.1 C37.1 C38.1 C39.1 C40.1 C41.1 C42.1 C43.1 C44.1 C48.1 C64.1 C65.1 C66.1 C67.1 C72.1 FB6.2 FB8.2 J1.1 J2.1 J3.1 J4.1 J9.1 R1.1 R2.1 R4.2 R12.1 R16.1 R17.1 R21.2 R23.1 R25.1 R29.1 R52.2 R55.1 R57.1 R59.1 R61.1 R63.1 R64.1 R65.1 R89.2 R91.2 R143.2 R144.2 R161.2 R162.2 R166.1 R169.1 R173.1 R175.1 R181.2 R182.1 R191.1 R195.1 R198.1 R202.1 R203.1 R212.2 R218.1 R219.1 R220.1 TP10.1 U3.8(VCCA) U9.1(OUT)
P3V3_IN: C33.1 C34.1 C63.1 C75.1 C77.2 C78.2 FB8.1 FB129.2 L1.2 R109.2 R168.2 R216.2 TP4.1 U2.75 U2.76 U2.77 U2.78 U2.79 U2.80 U2.81 U9.5(IN)
P3V3_PG: R212.1 U7.9(PG)
P3V3EN: C35.2 R105.1 R110.1 U7.11(EN)
P5V: C10.1 C12.1 C16.1 C20.1 C21.1 C24.1 C26.1 C29.2 C49.1 C51.1 C73.1 C76.1 EC1.1 FB2.1 FB4.2 FB5.1 FB7.2 FB9.1 J9.27 Q1.5(D2) R71.2 R80.1 R93.1 R106.2 R110.2 TP2.1 U6.5(IN) U7.2(VIN1) U7.3(VIN2) U7.4(VIN3) U7.5(VIN4) U8.1(OUT)
P5V_ADC: C74.2 FB9.2 U5.2(V+)
P5VSB: C17.1 C19.1 C59.1 F1.2 FB4.1 Q1.8(D1) R78.2 R149.1 R151.2 R152.2 R156.2 TP1.1
VBAT: C15.2 R51.2 U2.74
ADC_IN0: R103.2 U5.15(OUTA) U5.16(-INA)
ADC_IN1: R77.2 U5.4(-INB) U5.5(OUTB)
ADC_IN2: R76.2 U5.8(OUTC) U5.9(-INC)
ADC_IN3: R102.2 U5.13(-IND) U5.14(OUTD)
ADCIN0: C31.2 R86.2 R99.1 R100.1 R104.1
ADCIN0+: R104.2 U5.1(+INA)
ADCIN1: C28.2 R85.2 R88.1 R97.1 R98.1
ADCIN1+: R88.2 U5.3(+INB)
ADCIN2: C27.2 R75.1 R84.2 R87.1 R96.1
ADCIN2+: R87.2 U5.10(+INC)
ADCIN3: C30.2 R83.2 R94.1 R95.1 R101.1
AI0: J9.29 R100.2
AI1: J9.31 R98.2
AI2: J9.33 R96.2
AI3: J9.35 R94.2
AI4: J9.30 R183.2
AI5: J9.36 R186.2
AI6: J9.34 R185.2
AI7: J9.32 R184.2
CAN0_RX: J4.4 R113.1
CAN0_TX: J4.3 R112.1
CAN1_RX: J4.6 R115.1
CAN1_TX: J4.5 R114.1
CAN2_RX: J3.4 R117.1
CAN2_TX: J3.3 R116.1
CAN3_RX: J3.6 R119.1
CAN3_TX: J3.5 R118.1
CARD_DET: D36.2 R142.2 SDCARD1.9(CARD DETECTION)
CH340_P5V: C13.1 C14.2 C52.2 C54.1 FB3.1 U3.1(VCCB) U4.7(VCC)
CH_RXD: R56.1 U4.9(RXD)
CH_TXD: R54.1 U4.8(TXD)
CHRXD: R128.1 U3.7(A1)
CHTXD: R130.1 U3.6(A2)
CPU_ADC_IN0: R99.2 R103.1 U2.102
CPU_ADC_IN1: R77.1 R97.2 U2.100
CPU_ADC_IN2: R75.2 R76.1 U2.98
CPU_ADC_IN3: R95.2 R102.1 U2.96
CPU_ADC_IN4: C68.2 R177.2 R183.1 U2.101
CPU_ADC_IN5: C71.2 R180.2 R186.1 U2.99
CPU_ADC_IN6: C70.2 R179.2 R185.1 U2.97
CPU_ADC_IN7: C69.2 R178.2 R184.1 U2.95
CPU_CAN0_RX: R113.2 U2.4
CPU_CAN0_TX: R112.2 U2.3
CPU_CAN1_RX: R115.2 U2.10
CPU_CAN1_TX: R114.2 U2.9
CPU_CAN2_RX: R117.2 U2.6
CPU_CAN2_TX: R116.2 U2.5
CPU_CAN3_RX: R119.2 U2.8
CPU_CAN3_TX: R118.2 U2.7
CPU_DOTESTN: R160.1 R161.1 U2.93
CPU_GMAC1_RXCLK: R193.2 U2.136
CPU_GMAC1_TXCLK_I: R47.2 U2.135
CPU_GMAC1_TXCLK_O: R49.2 U2.134
CPU_I2C0_SCL: R203.2 R204.2 U2.133
CPU_I2C0_SDA: R201.2 R202.2 U2.132
CPU_I2C1_SCL: R58.1 R64.2 R206.2 U2.121
CPU_I2C1_SDA: R60.1 R65.2 R205.2 U2.120
CPU_I2C2_SCL: R55.2 R207.2 U2.125
CPU_I2C2_SDA: R57.2 R208.2 U2.124
CPU_I2C3_SCL: R59.2 R209.2 U2.123
CPU_I2C3_SDA: R61.2 R210.2 U2.122
CPU_I2S_BCLK: J9.21 U2.118
CPU_I2S_DI: J9.23 U2.115
CPU_I2S_DO: J9.24 U2.116
CPU_I2S_LR: J9.26 U2.114
CPU_I2S_MCLK: J9.25 U2.117
CPU_JTAG_SEL: R162.1 R163.1 U2.88
CPU_JTAG_TCK: R170.1 U2.91
CPU_JTAG_TDI: R174.2 U2.89
CPU_JTAG_TDO: R176.1 U2.87
CPU_JTAG_TMS: R167.1 U2.92
CPU_JTAG_TRST: R172.1 U2.90
CPU_LCD_CLK: FB1.1 U2.33
CPU_LCD_DATA0: R13.1 U2.34
CPU_LCD_DATA1: R12.2 R36.1 U2.35
CPU_LCD_DATA2: R10.1 R11.1 U2.36
CPU_LCD_DATA3: R9.1 R34.1 U2.37
CPU_LCD_DATA4: R23.2 R32.1 U2.38
CPU_LCD_DATA5: R25.2 R27.1 U2.39
CPU_LCD_DATA6: R30.1 U2.40
CPU_LCD_DATA7: R28.1 R29.2 U2.41
CPU_LCD_DATA8: R40.1 U2.42
CPU_LCD_DATA9: R145.1 U2.43
CPU_LCD_DATA10: R31.1 U2.44
CPU_LCD_DATA11: R33.1 U2.45
CPU_LCD_DATA12: R35.1 U2.46
CPU_LCD_DATA13: R37.1 U2.47
CPU_LCD_DATA14: R39.1 U2.48
CPU_LCD_DATA15: R38.1 U2.49
CPU_LCD_DATA16: R41.1 U2.50
CPU_LCD_DATA17: R43.1 U2.51
CPU_LCD_DATA18: R45.1 U2.52
CPU_LCD_DATA19: R50.1 U2.53
CPU_LCD_DATA20: R48.1 U2.54
CPU_LCD_DATA21: R46.1 U2.55
CPU_LCD_DATA22: R44.1 U2.56
CPU_LCD_DATA23: R42.1 U2.57
CPU_LCD_EN: R14.1 U2.32
CPU_LCD_HSYNC: R26.1 U2.31
CPU_LCD_VSYNC: R15.1 U2.30
CPU_SDIO1_CLK: R136.1 U2.18
CPU_SDIO1_CMD: R135.1 U2.17
CPU_SDIO1_DATA0: R138.1 U2.16
CPU_SDIO1_DATA1: R140.1 U2.15
CPU_SDIO1_DATA2: R133.1 U2.14
CPU_SDIO1_DATA3: R134.1 U2.13
CPU_SPI0_CLK: R215.2 U2.69
CPU_SPI0_CSN: R213.1 U2.70
CPU_SPI0_MISO: R214.1 U2.68
CPU_SPI0_MOSI: R217.2 U2.67
CPU_SPI1_CLK: R190.2 U2.66
CPU_SPI1_CSN: R187.2 R219.2 U2.64
CPU_SPI1_MISO: R189.2 U2.65
CPU_SPI1_MOSI: R188.2 U2.63
CPU_SPI2_CLK: R8.1 R127.2 U2.61
CPU_SPI2_CSN: R22.1 R124.2 R220.2 U2.59
CPU_SPI2_MISO: R18.1 R126.2 U2.62
CPU_SPI2_MOSI: R19.1 R125.2 U2.60
CPU_TIM1_CH1: R142.1 R144.1 U2.28
CPU_TIM1_CH1N: R16.2 R24.2 U2.27
CPU_TIM1_CH2: R6.2 R17.2 U2.24
CPU_TIM1_CH2N: R3.2 U2.23
CPU_TIM1_CH3: R5.2 U2.26
CPU_TIM1_CH3N: R120.2 U2.25
CPU_TIM2_CH1: R121.2 U2.22
CPU_TIM2_CH2: R122.2 U2.21
CPU_TIM2_CH3: R123.2 U2.20
CPU_UART0_RXD: R130.2 R131.2 U2.1
CPU_UART0_TXD: R128.2 R132.2 U2.2
CPU_UART1_RXD: R192.2 U2.128
CPU_UART1_TXD: R194.2 U2.129
CPU_UART2_RXD: R196.2 U2.126
CPU_UART2_TXD: R197.2 U2.127
CPU_UART3_RXD: R199.2 U2.130
CPU_UART3_TXD: R200.2 U2.131
CPU_USB0_DM: CHK1.2 R68.2 U2.110
CPU_USB0_DP: CHK1.1 R66.2 U2.111
CPU_USB0_DRVBUS: R82.1 R89.1 R90.1 U2.105
CPU_USB0_ID: D23.1 J8.1 U2.107
CPU_USB1_DM: CHK2.2 R70.2 U2.108
CPU_USB1_DP: CHK2.1 R69.2 U2.109
CPU_USB1_OC: Q5.3(DRAIN) R181.1 U2.106
DCIN_DET: CON4.3(GND#3) R165.1
EJTAG_TCK: R169.2 R170.2 TP6.1
EJTAG_TDI: R174.1 R175.2 TP8.1
EJTAG_TDO: R176.2 R182.2 TP9.1
EJTAG_TMS: R166.2 R167.2 TP5.1
EJTAG_TRST: R171.2 R172.2 R173.2 TP7.1
GMAC1_RXCLK: J9.5 R193.1
GMAC1_TXCLK_I: J9.4 R47.1
GMAC1_TXCLK_O: J9.3 R49.1
GPIO82: CON5.39 R6.1
GPIO83: C2.1 D4.2 KEY2.2 R4.1 R5.1
GPIO84: CON5.34 R24.1
GPIO85: D1.C(CATHODE) D2.2 R2.2 R3.1
I2C0_SCL: J9.13 R204.1
I2C0_SDA: J9.14 R201.1
I2C1_SCL: J9.15 R206.1
I2C1_SDA: J9.16 R205.1
I2C2_SCL: J9.17 R207.1
I2C2_SDA: J9.18 R208.1
I2C3_SCL: J9.19 R209.1
I2C3_SDA: J9.20 R210.1
LCD_B0: CON5.21 R13.2
LCD_B1: CON5.22 R36.2
LCD_B2: CON5.23 R11.2
LCD_B3: CON5.24 R34.2
LCD_B4: CON5.25 R32.2
LCD_B5: CON5.26 R27.2
LCD_B6: CON5.27 R30.2
LCD_B7: CON5.28 R28.2
LCD_CLK: C3.1 CON5.30 FB1.2
LCD_DE: CON5.33 R14.2
LCD_G0: CON5.12 R40.2
LCD_G1: CON5.13 R145.2
LCD_G2: CON5.14 R31.2
LCD_G3: CON5.15 R33.2
LCD_G4: CON5.16 R35.2
LCD_G5: CON5.17 R37.2
LCD_G6: CON5.18 R39.2
LCD_G7: CON5.19 R38.2
LCD_HSYNC: CON5.31 R26.2
LCD_R0: CON5.3 R41.2
LCD_R1: CON5.4 R43.2
LCD_R2: CON5.5 R45.2
LCD_R3: CON5.6 R50.2
LCD_R4: CON5.7 R48.2
LCD_R5: CON5.8 R46.2
LCD_R6: CON5.9 R44.2
LCD_R7: CON5.10 R42.2
LCD_RESETN: D17.A(ANODE) R7.1 R20.1
LCD_VSYNC: CON5.32 R15.2
MB_PWREN: R157.1 U2.113
MRESET#: C1.1 D3.2 KEY1.2 R211.1 U2.71
P0_MDIO0+: CON1.2 D14.2 U2.138
P0_MDIO0-: CON1.3 D13.2 U2.139
P0_MDIO1+: CON1.4 D12.2 U2.140
P0_MDIO1-: CON1.7 D11.2 U2.141
P0_MDIO2+: CON1.5 D10.2 U2.142
P0_MDIO2-: CON1.6 D9.2 U2.143
P0_MDIO3+: CON1.8 D8.2 U2.144
P0_MDIO3-: CON1.9 D7.2 U2.145
PHY0_LED0: C46.2 R141.2 U2.148
PHY0_LED1: C5.2 D5.A(ANODE) U2.147
PHY0_LED2: C7.2 D6.A(ANODE) U2.146
PLTRESETN: D17.C(CATHODE) U2.72
PWM0: J2.6 R120.1
PWM1: J2.5 R121.1
PWM2: J2.4 R122.1
PWM3: J2.3 R123.1
SDIO1_CLK: D33.2 R136.2 SDCARD1.5(CLK)
SDIO1_CMD: D32.2 R135.2 SDCARD1.3(CMD)
SDIO1_DATA0: D34.2 R138.2 SDCARD1.7(DAT0)
SDIO1_DATA1: D35.2 R140.2 SDCARD1.8(DAT1)
SDIO1_DATA2: D30.2 R133.2 SDCARD1.1(DAT2)
SDIO1_DATA3: D31.2 R134.2 SDCARD1.2(CD/DAT3)
SPI0_CLK: D26.2 J10.6 R215.1
SPI0_CSN: D24.2 J10.1 R213.2
SPI0_MISO: D25.2 J10.3 R214.2
SPI0_MOSI: D27.2 J10.8 R217.1
SPI1_CLK: J9.40 R190.1
SPI1_CSN: J9.37 R187.1
SPI1_MISO: J9.39 R189.1
SPI1_MOSI: J9.38 R188.1
SPI2_CLK: J1.6 R127.1
SPI2_CSN: J1.3 R124.1
SPI2_MISO: J1.5 R126.1
SPI2_MOSI: J1.4 R125.1
T_CS/CT_RST: CON5.35 R20.2 R21.1 R22.2
T_MOSI/CT_SDA: CON5.36 R19.2 R60.2
T_SCL/CT_SCL: CON5.38 R8.2 R58.2
UART0_RXD: D28.2 D38.A(ANODE) R131.1 R218.2
UART0_TXD: D29.2 J5.2 R132.1
UART1_RXD: D39.A(ANODE) R191.2 R192.1
UART1_TXD: J9.7 R194.1
UART1RXD: D39.C(CATHODE) J9.8
UART2_RXD: D40.A(ANODE) R195.2 R196.1
UART2_TXD: J9.9 R197.1
UART2RXD: D40.C(CATHODE) J9.10
UART3_RXD: D41.A(ANODE) R198.2 R199.1
UART3_TXD: J9.11 R200.1
UART3RXD: D41.C(CATHODE) J9.12
USB0_DM: CHK1.3 CON2.6(CON_PIN[16]) D20.1 R68.1
USB0_DP: CHK1.4 CON2.7(CON_PIN[17]) D19.1 R66.1
USB1_DM: CHK2.3 CON2.2(CON_PIN[12]) D22.1 R70.1
USB1_DP: CHK2.4 CON2.3(CON_PIN[13]) D21.1 R69.1
USB_DN: CON3.A7(DN1) CON3.B7(DN2) D18.1 U4.2(UD-)
USB_DP: CON3.A6(DP1) CON3.B6(DP2) D16.1 U4.1(UD+)
USB_PWR1: C23.1 CON2.5(CON_PIN[15]) EC2.1 U6.1(VOUT)
USB_PWR2: C25.1 CON2.1(CON_PIN[11]) EC3.1 FB5.2 R81.1
USB_VBUS: C18.2 C53.1 C57.1 CON3.A4(VBUS1) CON3.A9(VBUS2) FB3.2 FB7.1 R153.2 R155.2 U8.5(IN)
USB_VBUSIN: R80.2 U2.104
N21480035: R106.1 R107.1 U7.13(ILMT)
N21480077: C79.1 U7.17(VCC)
N21480090: C32.2 L1.1 U7.6(SW1) U7.19(SW2) U7.20(SW3)
N21480094: C32.1 U7.1(BST)
N21480120: C80.1 U7.15(BYP)
N21480193: C36.1 R108.1 R109.1 U7.14(FB)
N21480303: D15.A(ANODE) R63.2
N21480386: R164.2 U9.3(ISET)
N21480402: C60.2 R157.2 R168.1 U9.4(EN)
N21480619: C36.2 R216.1
N21733684: CON4.1(GND#1) F1.1 J7.1
N21758418: C8.1 CON1.1
N21758422: CON1.11 R143.1
N21758424: CON1.12 R141.1
N21758431: D5.C(CATHODE) D6.C(CATHODE) R137.2
N21758441: CON1.14 R137.1
N21758443: CON1.13 R139.1
N21788378: C50.1 U4.10(V3)
N21805568: J6.1 R51.1
N21821121: R56.2 U3.2(B1)
N21821123: R54.2 U3.3(B2)
N21821131: R52.1 R53.2 U3.4(OE)
N21821540: CON3.A5(CC1) R62.1
N21821542: CON3.B5(CC2) R67.1
N21838330: C9.1 C11.1 CON5.1 CON5.2 FB2.2
N21838391: CON5.40 R7.2
N21838396: CON5.37 R18.2
N21863620: D1.A(ANODE) R1.2
N21889419: C56.1 Q3.3(DRAIN) R153.1 U8.4(EN)
N21889500: C61.1 Q3.1(GATE) R155.1 R156.1 R159.2 R165.2
N21934934: C45.1 FB6.1 SDCARD1.4(VDD)
N21940880: Q5.1(GATE) R81.2
N21942133: R91.1 U6.3(FAULT#)
N21942139: Q2.3(DRAIN) R90.2 R92.2 R93.2 U6.4(EN)
N21942279: Q2.1(GATE) R82.2
N21952179: C81.2 FB129.1 J10.2
N21952209: J10.5 R211.2
N21978619: MH1.1 R111.2
N22007036: R101.2 U5.12(+IND)
N22046592: D38.C(CATHODE) J5.3
N22064922: D37.2(REF) R147.2 R149.2
N22064940: C58.1 Q4.1(GATE) R154.1 R221.2
N22064950: D37.1(CATHODE) R151.1 R221.1
N22064960: Q4.3(DRAIN) R79.1 R158.2
N22065002: C22.2 Q1.1(S1) Q1.3(S2) R73.1
N22065004: C22.1 R72.1 R73.2 R74.1 R78.1 R79.2
N22065156: C55.1 R152.1
N22065188: Q1.2(G1) R72.2
N22065200: Q1.4(G2) R74.2
N218893952: R148.2 U8.3(ISET)

Pads without a net: CON3 A8 B8; J10 4; KEY1 3; KEY2 3; MK1 1; MK2 1; MK3 1; MK4 1; MK5 1; MK6 1; MK7 1; MK8 1; U4 4 5 6; U5 6 7; U7 10 12 16

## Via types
v1: diameter 0.457, hole 0.254, TOP to BOTTOM, 416 vias

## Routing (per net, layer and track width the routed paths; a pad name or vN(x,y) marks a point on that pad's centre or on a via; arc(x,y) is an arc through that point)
GND: length 147.9
  TOP w0.254: U5.11 51.69,15.48 v1(51.94,15.22)
  TOP w0.381: KEY1.1 11.15,63.34 D3.1 ; R105.2 C35.1 v1(10.79,9.07) ; D20.2 D21.2 v1(74.8,24) ; C5.1 v1(71.88,55.81) ; C6.2 13.44,56.44 v1(13.71,56.18) ; D19.2 v1(74.8,28.06) 74.75,28.06 D15.C ; C3.2 v1(36.96,58.48) ; v1(31.37,61.02) R10.2 R9.2 ; R67.2 v1(12.16,26.82) ; v1(69.47,41.71) D14.1 70.16,40.63 C8.2 ; D27.1 D26.1 ; D26.1 D25.1 D24.1 ; D26.1 30.99,7.42 v1(31.11,7.29) ; v1(15.24,60.76) C2.2 14.16,61.52 D4.1 ; C1.2 5.84,61.02 v1(5.84,60.63) ; R62.2 11.46,29.55 D16.2 v1(12.16,29.49) ; v1(69.47,44.51) D12.1 D13.1 ; CON5.29 v1(7.49,51.17) ; v1(49.4,13.64) C30.1 C27.1 ; U2.137 v1(66.94,45.09) ; U2.119 v1(66.94,28.89) ; v1(44.7,16.82) 45.57,16.82 R86.1 ; CON5.11 v1(7.49,42.17) ; C28.1 C31.1 v1(54.99,13.64) ; v1(16.13,5.9) R108.2 R107.2 ; U2.94 v1(49.29,20.23) ; CON5.20 v1(7.49,46.67) ; C13.2 v1(24.13,31.55) ; v1(77.72,13.9) 77.86,14.04 80.51,14.04 R92.1 ; D11.1 D10.1 v1(69.47,47.3) ; D2.1 v1(18.73,64.83) ; R83.1 v1(38.58,17.43) ; U2.19 v1(48.39,57.35) ; U2.11 v1(55.59,57.35) ; U3.5 v1(17.31,34.3) ; v1(57.39,20.12) U2.103 ; U2.112 v1(67.07,22.59) ; D23.2 61.92,16.48 J8.2 ; U2.12 v1(54.69,57.35) ; U2.58 v1(29.83,36.99) ; D9.1 D8.1 v1(69.47,50.09) ; v1(28.19,24.57) 29.27,23.49 U2.73 ; U2.29 v1(39.39,57.35) ; R53.1 24.46,35.16 v1(24.89,35.16) ; R84.1 v1(41,17.43) ; v1(42.29,16.82) 43.15,16.82 R85.1 ; U4.3 v1(18.03,28.38) ; Q2.2 v1(68.01,14.66) ; D18.2 v1(12.16,28.09) ; D7.1 v1(69.47,51.49) ; C7.1 v1(71.88,52.76)
  TOP w0.508: D22.2 v1(74.8,21.07) ; 8,22.41 8,23.04 7.31,23.73 CON3.A12
  TOP w0.635: CON3.A1 7.19,30.23 7.75,30.79 v1(7.75,32.69)
  BOTTOM w0.381: 24.96,23.11 Q4.2 24.26,22.45 C60.1 R158.1 ; 24.96,23.11 26.6,23.11 C58.2 ; 24.96,23.11 v1(25.78,23.93) ; D31.1 v1(16.46,54.08) ; C45.2 v1(16.39,51.32) ; D34.1 v1(16.46,48.5) ; R139.2 v1(85.72,47.43) ; v1(24.51,30.15) 24.74,29.93 D37.3 ; J3.2 65.23,62.23 C41.2 65.31,61.39 C44.2 ; C70.1 40.39,16.57 R84.1 v1(41,17.43) ; D32.1 v1(16.46,52.69) ; C48.2 19.81,31.81 C50.2 ; C37.2 v1(39.62,64.57) ; J4.2 80.85,62.33 C40.2 80.9,61.55 C43.2 ; R171.1 v1(58.93,18.34) ; D29.1 v1(74.42,55.17) ; R85.1 43.15,16.82 v1(42.29,16.82) C69.1 ; v1(5.59,25.07) 6.1,25.58 C57.2 8.89,25.58 C56.2 ; v1(24.13,31.55) 23.24,30.66 R147.1 ; v1(84.07,15.3) 84.26,15.11 Q5.2 ; v1(38.58,17.43) R83.1 37.97,16.57 C71.1 ; D35.1 v1(16.46,47.1) ; J2.2 49.61,62.48 C39.2 49.68,61.77 C42.2 ; SDCARD1.12 v1(14.99,44.12) ; R163.2 41.28,20.38 v1(41.28,20.12) ; v1(52.96,15.22) 53.52,14.66 C74.1 ; J1.2 33.99,63.48 34.42,63.05 ; v1(3.69,43.37) SDCARD1.14 v1(3.69,45.38) ; R160.2 49.28,20.24 v1(49.29,20.23) ; D33.1 v1(16.46,49.89) ; C46.1 v1(84.33,45.65) ; C59.2 13.97,24.57 12.54,24.57 Q3.2 11.5,23.36 10.97,22.84 v1(10.97,22.41) ; D36.1 v1(16.46,45.7) ; D28.1 v1(76.96,55.17) ; SDCARD1.6 v1(15.11,48.87) ; R86.1 45.57,16.82 v1(44.7,16.82) C68.1 ; SDCARD1.11 14.36,58.98 v1(14.48,58.86) ; D30.1 v1(16.46,55.48)
  BOTTOM w0.508: v1(9.78,63.43) 9.78,63.05 R111.1 ; v1(20.32,10.85) 20.32,10.09 C81.1
  vias: v1(0.76,61.27) v1(0.76,59.87) v1(0.76,58.48) v1(4.19,26.6) v1(4.19,25.58) v1(4.19,24.57) v1(5.46,33.96) v1(5.46,20.25) v1(5.46,18.98) v1(5.84,59.36) v1(6.73,20.25) v1(6.73,18.98) v1(6.86,33.96) v1(7.49,7.29) v1(7.49,5.77) v1(9.02,7.29) v1(9.02,5.77) v1(9.78,64.95) v1(9.78,64.19) v1(10.29,32.69) v1(10.41,7.29) v1(10.41,5.77) v1(10.97,21.39) v1(10.97,20.5) v1(11.94,21.39) v1(11.94,20.5) v1(14.22,8.95) v1(15.24,8.95) v1(16.77,11.31) v1(17.4,29.77) v1(17.4,26.98) v1(18.67,29.77) v1(18.67,26.98) v1(19.43,14.79) v1(20.19,14.79) v1(21.59,10.85) v1(22.86,10.85) v1(24.51,29.14) v1(28.19,22.53) v1(28.19,21.52) v1(29.08,18.6) v1(29.08,17.71) v1(29.08,16.82) v1(29.97,17.71) v1(29.97,16.82) v1(31.11,6.15) v1(33.02,11.36) v1(33.02,9.96) v1(33.02,8.56) v1(33.02,7.29) v1(33.02,6.15) v1(38.73,20.12) v1(38.73,19.23) v1(40,20.12) v1(40,19.23) v1(41.28,19.23) v1(51.94,16.23) v1(52.45,15.73) v1(52.96,16.23) v1(70.87,15.42) v1(70.87,14.41) v1(70.87,13.39) v1(72.26,46.54) v1(72.26,43.87) v1(77.72,15.68) v1(77.72,14.79) v1(78.49,17.96) v1(80.01,17.96) v1(81.66,17.96) v1(83.19,17.96) v1(83.19,16.95) v1(83.95,55.55) v1(85.22,56.57) v1(85.22,55.55) v1(85.98,38.79) v1(85.98,37.39) v1(86.49,55.55) v1(87.38,38.79) v1(87.38,37.39)
GND_EARTH_L: length 40.2
  TOP w1.016: CON3.S1 CON3.S3 CON3.S4 CON3.S2
  TOP w1.524: CON3.S4 1.68,10.82 MH3.1
  BOTTOM w1.016: CON3.S3 CON3.S1 ; CON3.S4 CON3.S2
GND_EARTH_R: length 2
  BOTTOM w1.016: CON1.10 79.88,52.88
P3V3: length 94.5
  TOP w0.381: R2.1 v1(18.67,63.56) ; R52.2 v1(24.89,36.63) ; v1(74.68,14.79) 74.68,14.41 R91.2 ; 66.17,11.23 65.53,11.87 R89.2 ; R63.1 v1(77.09,29.27) ; R4.2 v1(16.26,60.76) ; R17.1 v1(42.16,61.02) ; R21.2 v1(11.05,56.44) C6.1 ; R16.1 v1(40.26,61.02) ; v1(74.3,38.92) 74.3,36.38 v1(72.14,34.22) R55.1 R57.1 R59.1 R61.1 R64.1 ; R29.1 v1(25.65,51.62) ; v1(25.65,53.9) R25.1 R23.1 ; U3.8 v1(17.31,32.35) ; R12.1 v1(33.66,61.02) ; R1.1 v1(18.67,66.1) ; R65.1 v1(72.14,28.5)
  BOTTOM w0.254: v1(74.68,14.79) 74.68,13.67 75.18,13.16 75.18,11.87 75.06,11.74 R198.1
  BOTTOM w0.381: C42.1 C39.1 51.61,62.56 J2.1 ; R181.2 83.31,15.04 84.96,13.39 v1(84.96,12.63) ; C43.1 82.7,62.26 C40.1 82.68,64.48 J4.1 ; v1(81.7,10.89) 82.17,11.36 R191.1 ; R195.1 77.47,11.36 v1(77.47,10.85) ; v1(74.59,10.89) R198.1 ; R182.1 R175.1 R173.1 58.67,17.2 59.56,18.09 59.56,19.11 ; R143.2 v1(86.49,44.38) ; C44.1 C41.1 67.23,62.3 J3.1 ; v1(17.31,32.35) 17.35,32.31 C48.1 ; R218.1 v1(78.23,55.05) ; R202.1 R203.1 v1(69.13,10.89) ; R162.2 R161.2 46.1,21.26 46.37,21.53 57.9,21.53 58.17,21.26 R166.1 ; R219.1 27.52,36.67 24.93,36.67 v1(24.89,36.63) ; v1(72.14,28.5) v1(72.14,34.22) ; C38.1 35.43,64.1 J1.1 36.71,63.94 37.21,63.94 C37.1 ; R144.2 v1(18.85,44.36) ; FB6.2 v1(22.1,51.32) ; R220.1 29.72,63.05 v1(30.35,63.05) ; R212.2 v1(13.33,9.71)
  vias: v1(11.18,13.64) v1(11.18,12.63) v1(12.45,13.64) v1(12.45,12.63) v1(13.72,13.64) v1(13.72,12.63) v1(65.66,55.68) v1(66.55,55.68) v1(67.44,55.68) v1(84.84,11.1) v1(84.84,10.22) v1(84.84,9.33)
